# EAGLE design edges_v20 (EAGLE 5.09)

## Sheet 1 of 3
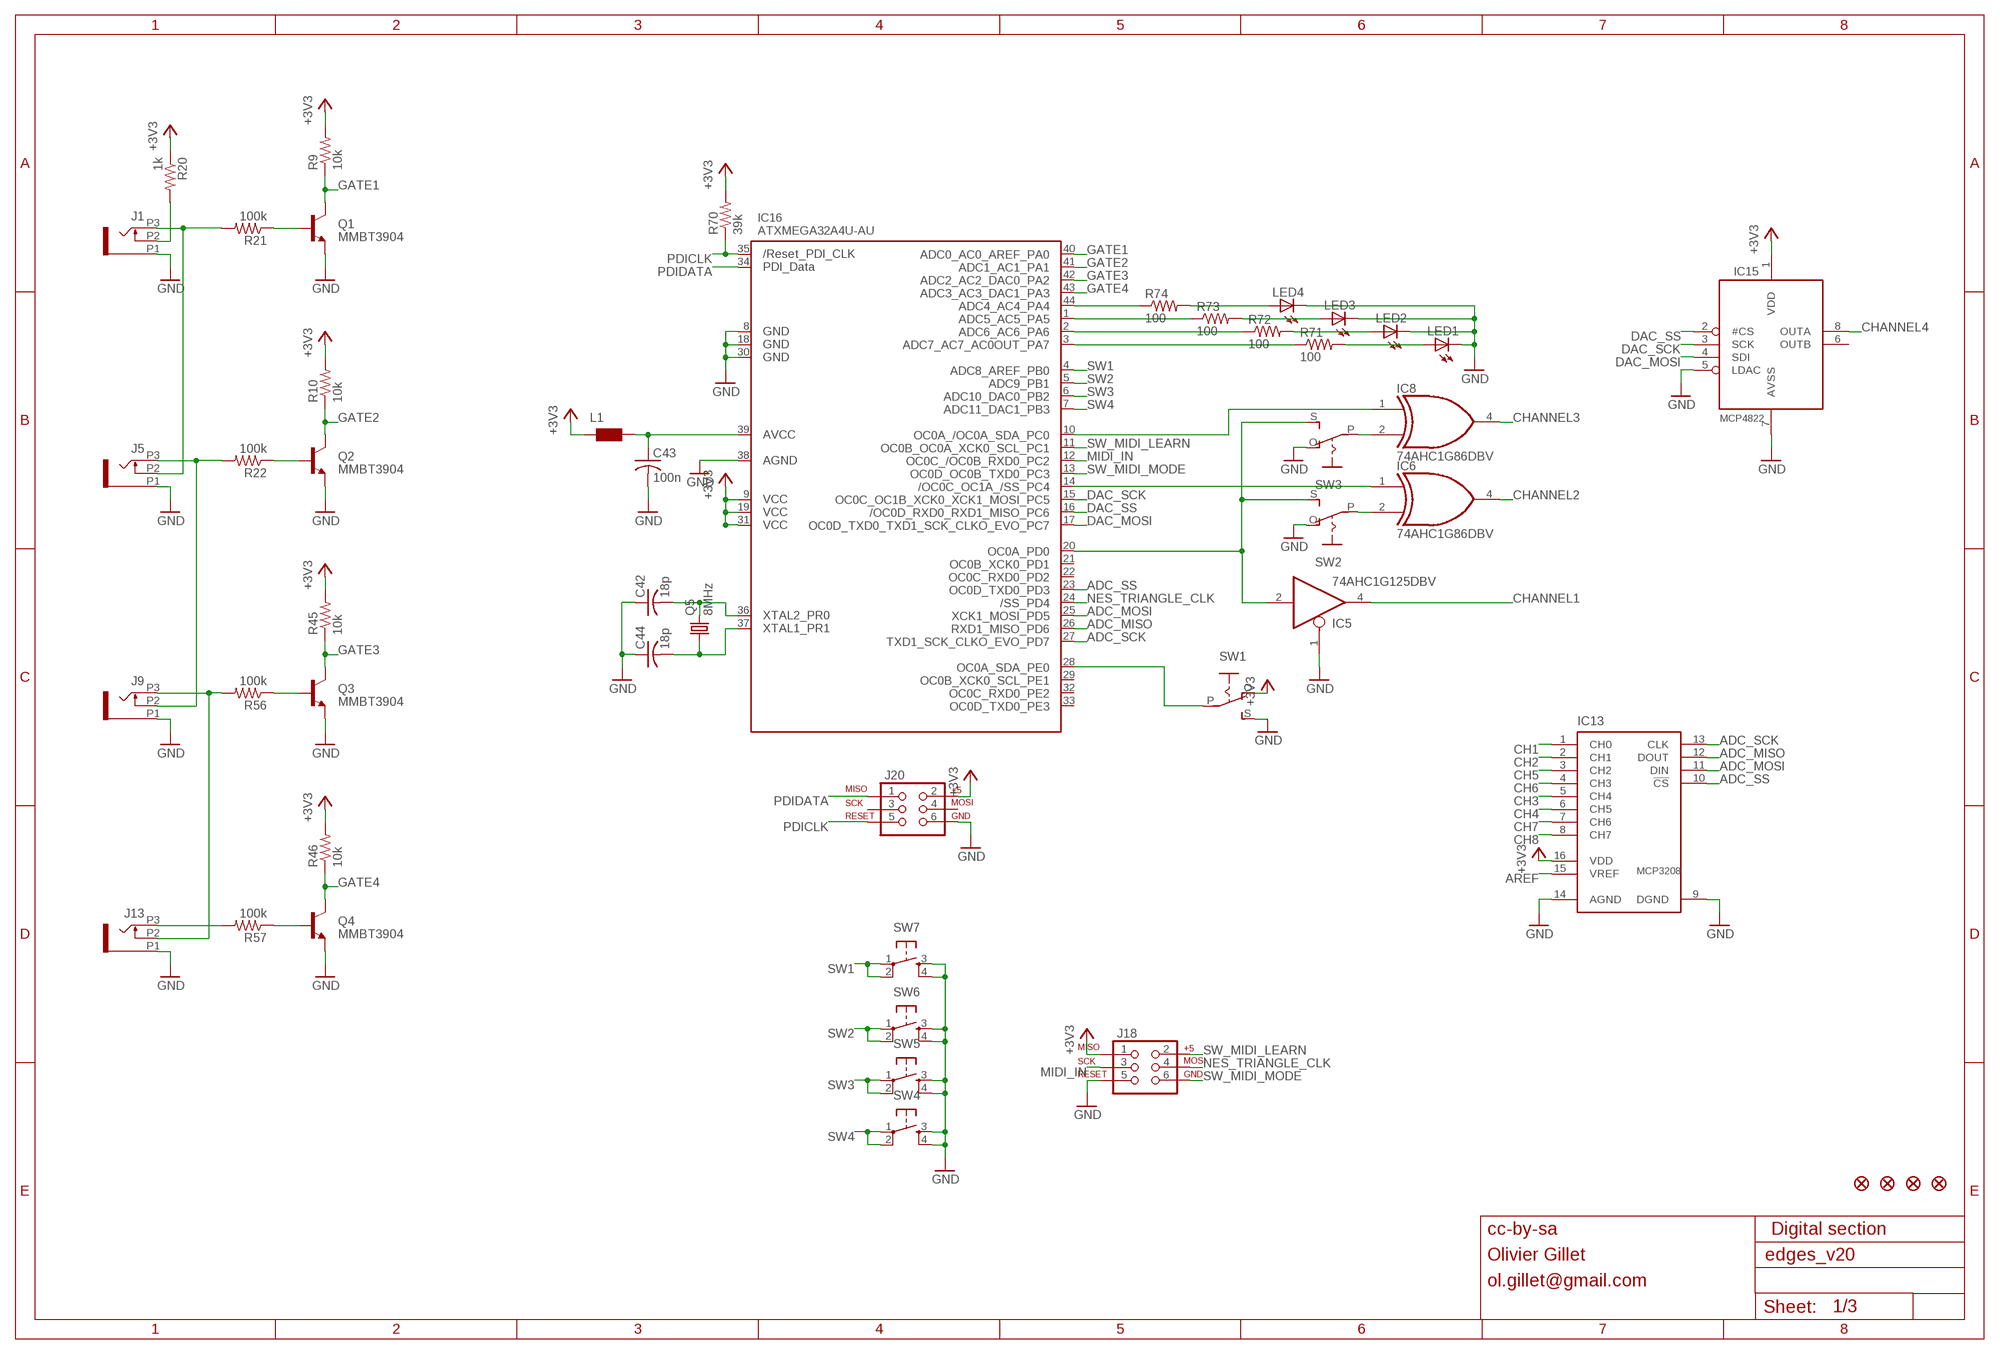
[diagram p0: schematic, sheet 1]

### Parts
C42  18p  C-USC0603  [C0603]
C43  100n  C-USC0603  [C0603]
C44  18p  C-USC0603  [C0603]
IC5  74AHC1G125DBV  [SOT23-5]
IC6  74AHC1G86DBV  [SOT23-5]
IC8  74AHC1G86DBV  [SOT23-5]
IC13  MCP3208  [SO16]
IC15  MCP4822  MCP4822SO08  [SO08]
IC16  ATXMEGA32A4U-AU  AVR_XMEGA_A4_44A  [TQFP44]
J1  PJ301_THONKICONN6  [WQP_PJ_301M6]
J5  PJ301_THONKICONN6  [WQP_PJ_301M6]
J9  PJ301_THONKICONN6  [WQP_PJ_301M6]
J13  PJ301_THONKICONN6  [WQP_PJ_301M6]
J18  AVR_SPI_PRG_6PTH  [2X3]
J20  AVR_SPI_PRG_6PTH  [2X3]
JP1  FIDUCIAL1X2  [FIDUCIAL-1X2]
JP2  FIDUCIAL1X2  [FIDUCIAL-1X2]
JP3  FIDUCIAL1X2  [FIDUCIAL-1X2]
JP4  FIDUCIAL1X2  [FIDUCIAL-1X2]
L1  WE-CBF_0603  [0603]
LED1  LED3MM  [LED3MM]
LED2  LED3MM  [LED3MM]
LED3  LED3MM  [LED3MM]
LED4  LED3MM  [LED3MM]
Q1  MMBT3904  MMBT3904LT1-NPN-SOT23-BEC  [SOT23-BEC]
Q2  MMBT3904  MMBT3904LT1-NPN-SOT23-BEC  [SOT23-BEC]
Q3  MMBT3904  MMBT3904LT1-NPN-SOT23-BEC  [SOT23-BEC]
Q4  MMBT3904  MMBT3904LT1-NPN-SOT23-BEC  [SOT23-BEC]
Q5  8MHz  CRYSTALHC49U70  [HC49U70]
R9  10k  R-US_R0603  [R0603]
R10  10k  R-US_R0603  [R0603]
R20  1k  R-US_R0603  [R0603]
R21  100k  R-US_R0603  [R0603]
R22  100k  R-US_R0603  [R0603]
R45  10k  R-US_R0603  [R0603]
R46  10k  R-US_R0603  [R0603]
R56  100k  R-US_R0603  [R0603]
R57  100k  R-US_R0603  [R0603]
R70  39k  R-US_R0603  [R0603]
R71  100  R-US_R0603  [R0603]
R72  100  R-US_R0603  [R0603]
R73  100  R-US_R0603  [R0603]
R74  100  R-US_R0603  [R0603]
SW1  S-ON-ONSMALL_SLIDE  [ES_100SP1T6B11M2QEH_SMALL]
SW2  S-ON-ONSMALL_SLIDE  [ES_100SP1T6B11M2QEH_SMALL]
SW3  S-ON-ONSMALL_SLIDE  [ES_100SP1T6B11M2QEH_SMALL]
SW4  TAC_SWITCHPTH  [TACTILE-PTH]
SW5  TAC_SWITCHPTH  [TACTILE-PTH]
SW6  TAC_SWITCHPTH  [TACTILE-PTH]
SW7  TAC_SWITCHPTH  [TACTILE-PTH]

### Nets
+3V3: IC13.16(VDD) IC15.1(VDD) IC16.9(VCC1) IC16.19(VCC2) IC16.31(VCC3) J18.1 J20.2 L1.1 R9.2 R10.2 R20.1 R45.2 R46.2 R70.2 SW1.O ; also sheet 3
ADC_MISO: IC13.12(DOUT) IC16.26(PD6)
ADC_MOSI: IC13.11(DIN) IC16.25(PD5)
ADC_SCK: IC13.13(CLK) IC16.27(PD7)
ADC_SS: IC13.10(!CS) IC16.23(PD3)
AREF: IC13.15(VREF) ; also sheet 3
CH1: IC13.1(CH0) ; also sheet 2
CH2: IC13.2(CH1) ; also sheet 2
CH3: IC13.5(CH4) ; also sheet 2
CH4: IC13.6(CH5) ; also sheet 2
CH5: IC13.3(CH2) ; also sheet 2
CH6: IC13.4(CH3) ; also sheet 2
CH7: IC13.7(CH6) ; also sheet 2
CH8: IC13.8(CH7) ; also sheet 2
CHANNEL1: IC5.4(O) ; also sheet 2
CHANNEL2: IC6.4(O) ; also sheet 2
CHANNEL3: IC8.4(O) ; also sheet 2
CHANNEL4: IC15.8(OUTA) ; also sheet 2
DAC_MOSI: IC15.4(SDI) IC16.17(PC7)
DAC_SCK: IC15.3(SCK) IC16.15(PC5)
DAC_SS: IC15.2(#CS) IC16.16(PC6)
GATE1: IC16.40(PA0) Q1.C R9.1
GATE1_IN: J1.P3 J5.P2 R21.2
GATE1_LED: LED4.A R74.2
GATE2: IC16.41(PA1) Q2.C R10.1
GATE2_IN: J5.P3 J9.P2 R22.2
GATE2_LED: LED3.A R73.2
GATE3: IC16.42(PA2) Q3.C R45.1
GATE3_IN: J9.P3 J13.P2 R56.2
GATE3_LED: LED2.A R72.2
GATE4: IC16.43(PA3) Q4.C R46.1
GATE4_IN: J13.P3 R57.2
GATE4_LED: LED1.A R71.2
GND: C42.1 C43.2 C44.1 IC5.1(OE) IC13.9(DGND) IC13.14(AGND) IC15.5(LDAC) IC15.7(AVSS) IC16.8(GND1) IC16.18(GND2) IC16.30(GND3) IC16.38(AGND) J1.P1 J5.P1 J9.P1 J13.P1 J18.5 J20.6 LED1.K(C) LED2.K(C) LED3.K(C) LED4.K(C) Q1.E Q2.E Q3.E Q4.E SW1.S SW2.O SW3.O SW4.3 SW4.4 SW5.3 SW5.4 SW6.3 SW6.4 SW7.3 SW7.4 ; also sheet 2,3
MIDI_IN: IC16.12(PC2) J18.3
N$1: Q1.B R21.1
N$2: Q2.B R22.1
N$3: Q3.B R56.1
N$5: IC16.44(PA4) R74.1
N$6: IC16.1(PA5) R73.1
N$7: IC16.2(PA6) R72.1
N$8: IC16.3(PA7) R71.1
N$12: J1.P2 R20.2
N$19: IC6.1(I0) IC16.14(PC4)
N$21: IC8.2(I1) SW3.P
N$24: IC6.2(I1) SW2.P
N$39: C43.1 IC16.39(AVCC) L1.2
N$41: IC8.1(I0) IC16.10(PC0)
N$48: IC5.2(I) IC16.20(PD0) SW2.S SW3.S
N$82: C44.2 IC16.37(PR1) Q5.1
N$83: C42.2 IC16.36(PR0) Q5.2
N$40000: Q4.B R57.1
NES_TRIANGLE_CLK: IC16.24(PD4) J18.4
PDICLK: IC16.35(RESET) J20.5 R70.1
PDIDATA: IC16.34(PDI_DATA) J20.1
SW1: IC16.4(PB0) SW7.1 SW7.2
SW2: IC16.5(PB1) SW6.1 SW6.2
SW3: IC16.6(PB2) SW5.1 SW5.2
SW4: IC16.7(PB3) SW4.1 SW4.2
SW_MIDI_LEARN: IC16.11(PC1) J18.2
SW_MIDI_MODE: IC16.13(PC3) J18.6
SYNC_SWITCH: IC16.28(PE0) SW1.P
Unconnected: IC15.6(OUTB) IC16.21(PD1) IC16.22(PD2) IC16.29(PE1) IC16.32(PE2) IC16.33(PE3) J20.3 J20.4

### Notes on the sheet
- cc-by-sa | Digital section
- Olivier Gillet
- ol.gillet@gmail.com

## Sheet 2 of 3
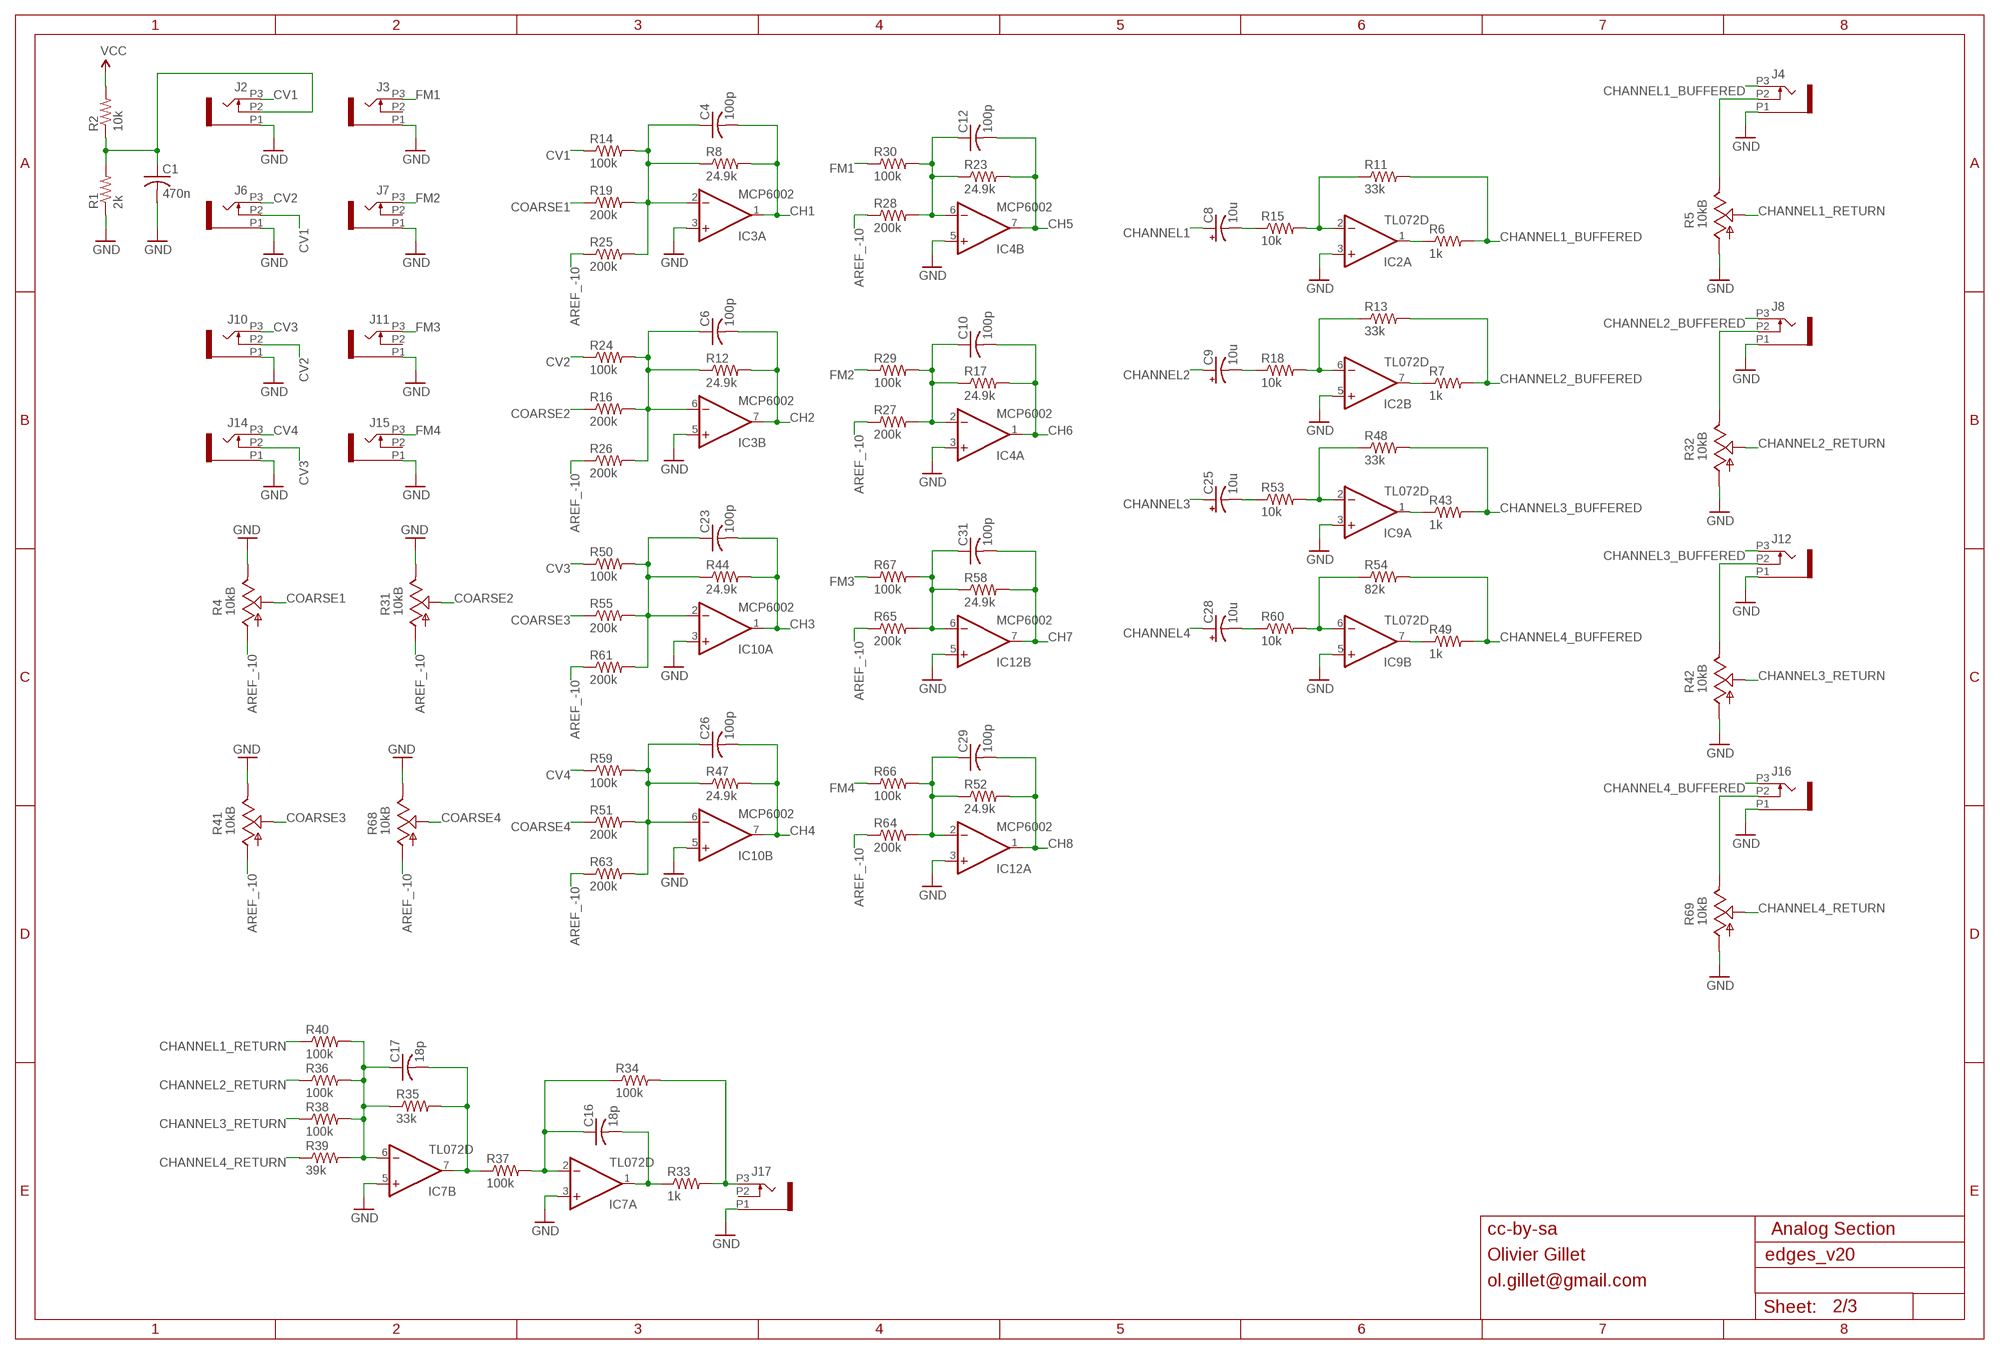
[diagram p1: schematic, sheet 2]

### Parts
C1  470n  C-USC0603  [C0603]
C4  100p  C-USC0603  [C0603]
C6  100p  C-USC0603  [C0603]
C8  10u  CPOL-USB  [PANASONIC_B]
C9  10u  CPOL-USB  [PANASONIC_B]
C10  100p  C-USC0603  [C0603]
C12  100p  C-USC0603  [C0603]
C16  18p  C-USC0603  [C0603]
C17  18p  C-USC0603  [C0603]
C23  100p  C-USC0603  [C0603]
C25  10u  CPOL-USB  [PANASONIC_B]
C26  100p  C-USC0603  [C0603]
C28  10u  CPOL-USB  [PANASONIC_B]
C29  100p  C-USC0603  [C0603]
C31  100p  C-USC0603  [C0603]
IC2  TL072D  [SO08]
IC3  MCP6002  TL072D  [SO08]
IC4  MCP6002  TL072D  [SO08]
IC7  TL072D  [SO08]
IC9  TL072D  [SO08]
IC10  MCP6002  TL072D  [SO08]
IC12  MCP6002  TL072D  [SO08]
J2  PJ301_THONKICONN6  [WQP_PJ_301M6]
J3  PJ301_THONKICONN6  [WQP_PJ_301M6]
J4  PJ301_THONKICONN6  [WQP_PJ_301M6]
J6  PJ301_THONKICONN6  [WQP_PJ_301M6]
J7  PJ301_THONKICONN6  [WQP_PJ_301M6]
J8  PJ301_THONKICONN6  [WQP_PJ_301M6]
J10  PJ301_THONKICONN6  [WQP_PJ_301M6]
J11  PJ301_THONKICONN6  [WQP_PJ_301M6]
J12  PJ301_THONKICONN6  [WQP_PJ_301M6]
J14  PJ301_THONKICONN6  [WQP_PJ_301M6]
J15  PJ301_THONKICONN6  [WQP_PJ_301M6]
J16  PJ301_THONKICONN6  [WQP_PJ_301M6]
J17  PJ301_THONKICONN6  [WQP_PJ_301M6]
R1  2k  R-US_R0603  [R0603]
R2  10k  R-US_R0603  [R0603]
R4  10kB  POT_USVERTICAL_PS  [ALPS_POT_VERTICAL_PS]
R5  10kB  POT_USVERTICAL_PS  [ALPS_POT_VERTICAL_PS]
R6  1k  R-US_R0603  [R0603]
R7  1k  R-US_R0603  [R0603]
R8  24.9k  R-US_R0603  [R0603]
R11  33k  R-US_R0603  [R0603]
R12  24.9k  R-US_R0603  [R0603]
R13  33k  R-US_R0603  [R0603]
R14  100k  R-US_R0603  [R0603]
R15  10k  R-US_R0603  [R0603]
R16  200k  R-US_R0603  [R0603]
R17  24.9k  R-US_R0603  [R0603]
R18  10k  R-US_R0603  [R0603]
R19  200k  R-US_R0603  [R0603]
R23  24.9k  R-US_R0603  [R0603]
R24  100k  R-US_R0603  [R0603]
R25  200k  R-US_R0603  [R0603]
R26  200k  R-US_R0603  [R0603]
R27  200k  R-US_R0603  [R0603]
R28  200k  R-US_R0603  [R0603]
R29  100k  R-US_R0603  [R0603]
R30  100k  R-US_R0603  [R0603]
R31  10kB  POT_USVERTICAL_PS  [ALPS_POT_VERTICAL_PS]
R32  10kB  POT_USVERTICAL_PS  [ALPS_POT_VERTICAL_PS]
R33  1k  R-US_R0603  [R0603]
R34  100k  R-US_R0603  [R0603]
R35  33k  R-US_R0603  [R0603]
R36  100k  R-US_R0603  [R0603]
R37  100k  R-US_R0603  [R0603]
R38  100k  R-US_R0603  [R0603]
R39  39k  R-US_R0603  [R0603]
R40  100k  R-US_R0603  [R0603]
R41  10kB  POT_USVERTICAL_PS  [ALPS_POT_VERTICAL_PS]
R42  10kB  POT_USVERTICAL_PS  [ALPS_POT_VERTICAL_PS]
R43  1k  R-US_R0603  [R0603]
R44  24.9k  R-US_R0603  [R0603]
R47  24.9k  R-US_R0603  [R0603]
R48  33k  R-US_R0603  [R0603]
R49  1k  R-US_R0603  [R0603]
R50  100k  R-US_R0603  [R0603]
R51  200k  R-US_R0603  [R0603]
R52  24.9k  R-US_R0603  [R0603]
R53  10k  R-US_R0603  [R0603]
R54  82k  R-US_R0603  [R0603]
R55  200k  R-US_R0603  [R0603]
R58  24.9k  R-US_R0603  [R0603]
R59  100k  R-US_R0603  [R0603]
R60  10k  R-US_R0603  [R0603]
R61  200k  R-US_R0603  [R0603]
R63  200k  R-US_R0603  [R0603]
R64  200k  R-US_R0603  [R0603]
R65  200k  R-US_R0603  [R0603]
R66  100k  R-US_R0603  [R0603]
R67  100k  R-US_R0603  [R0603]
R68  10kB  POT_USVERTICAL_PS  [ALPS_POT_VERTICAL_PS]
R69  10kB  POT_USVERTICAL_PS  [ALPS_POT_VERTICAL_PS]

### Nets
AREF_-10: R4.P$3(A) R25.1 R26.1 R27.1 R28.1 R31.P$3(A) R41.P$3(A) R61.1 R63.1 R64.1 R65.1 R68.P$3(A) ; also sheet 3
CH1: C4.2 IC3.1(A:OUT) R8.2 ; also sheet 1
CH2: C6.2 IC3.7(B:OUT) R12.2 ; also sheet 1
CH3: C23.2 IC10.1(A:OUT) R44.2 ; also sheet 1
CH4: C26.2 IC10.7(B:OUT) R47.2 ; also sheet 1
CH5: C12.2 IC4.7(B:OUT) R23.2 ; also sheet 1
CH6: C10.2 IC4.1(A:OUT) R17.2 ; also sheet 1
CH7: C31.2 IC12.7(B:OUT) R58.2 ; also sheet 1
CH8: C29.2 IC12.1(A:OUT) R52.2 ; also sheet 1
CHANNEL1: C8.+ ; also sheet 1
CHANNEL1_BUFFERED: J4.P3 R6.2 R11.2
CHANNEL1_RETURN: R5.P$2(S) R40.1
CHANNEL2: C9.+ ; also sheet 1
CHANNEL2_BUFFERED: J8.P3 R7.2 R13.2
CHANNEL2_RETURN: R32.P$2(S) R36.1
CHANNEL3: C25.+ ; also sheet 1
CHANNEL3_BUFFERED: J12.P3 R43.2 R48.2
CHANNEL3_RETURN: R38.1 R42.P$2(S)
CHANNEL4: C28.+ ; also sheet 1
CHANNEL4_BUFFERED: J16.P3 R49.2 R54.2
CHANNEL4_RETURN: R39.1 R69.P$2(S)
COARSE1: R4.P$2(S) R19.1
COARSE2: R16.1 R31.P$2(S)
COARSE3: R41.P$2(S) R55.1
COARSE4: R51.1 R68.P$2(S)
CV1: J2.P3 J6.P2 R14.1
CV2: J6.P3 J10.P2 R24.1
CV3: J10.P3 J14.P2 R50.1
CV4: J14.P3 R59.1
FM1: J3.P3 R30.1
FM2: J7.P3 R29.1
FM3: J11.P3 R67.1
FM4: J15.P3 R66.1
GND: C1.2 IC2.3(A:+IN) IC2.5(B:+IN) IC3.3(A:+IN) IC3.5(B:+IN) IC4.3(A:+IN) IC4.5(B:+IN) IC7.3(A:+IN) IC7.5(B:+IN) IC9.3(A:+IN) IC9.5(B:+IN) IC10.3(A:+IN) IC10.5(B:+IN) IC12.3(A:+IN) IC12.5(B:+IN) J2.P1 J3.P1 J4.P1 J6.P1 J7.P1 J8.P1 J10.P1 J11.P1 J12.P1 J14.P1 J15.P1 J16.P1 J17.P1 R1.1 R4.P$1(E) R5.P$3(A) R31.P$1(E) R32.P$3(A) R41.P$1(E) R42.P$3(A) R68.P$1(E) R69.P$3(A) ; also sheet 1,3
MIX: J17.P3 R33.2 R34.2
N$4: J8.P2 R32.P$1(E)
N$9: C23.1 IC10.2(A:-IN) R44.1 R50.2 R55.2 R61.2
N$11: C10.1 IC4.2(A:-IN) R17.1 R27.2 R29.2
N$13: C26.1 IC10.6(B:-IN) R47.1 R51.2 R59.2 R63.2
N$15: C31.1 IC12.6(B:-IN) R58.1 R65.2 R67.2
N$18: C29.1 IC12.2(A:-IN) R52.1 R64.2 R66.2
N$20: C8.- R15.1
N$22: IC2.2(A:-IN) R11.1 R15.2
N$23: IC2.1(A:OUT) R6.1
N$25: C9.- R18.1
N$26: IC2.6(B:-IN) R13.1 R18.2
N$27: IC2.7(B:OUT) R7.1
N$28: C25.- R53.1
N$29: C12.1 IC4.6(B:-IN) R23.1 R28.2 R30.2
N$30: IC9.2(A:-IN) R48.1 R53.2
N$31: IC9.1(A:OUT) R43.1
N$32: C28.- R60.1
N$33: IC9.6(B:-IN) R54.1 R60.2
N$34: IC9.7(B:OUT) R49.1
N$35: C17.1 IC7.6(B:-IN) R35.1 R36.2 R38.2 R39.2 R40.2
N$36: C16.1 IC7.2(A:-IN) R34.1 R37.2
N$37: C16.2 IC7.1(A:OUT) R33.1
N$40: J4.P2 R5.P$1(E)
N$42: C17.2 IC7.7(B:OUT) R35.2 R37.1
N$43: J12.P2 R42.P$1(E)
N$44: J16.P2 R69.P$1(E)
N$45: C6.1 IC3.6(B:-IN) R12.1 R16.2 R24.2 R26.2
N$46: C1.1 J2.P2 R1.2 R2.1
N$50: C4.1 IC3.2(A:-IN) R8.1 R14.2 R19.2 R25.2
VCC: R2.2 ; also sheet 3
Unconnected: J3.P2 J7.P2 J11.P2 J15.P2 J17.P2

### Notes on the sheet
- cc-by-sa | Analog Section
- Olivier Gillet
- ol.gillet@gmail.com

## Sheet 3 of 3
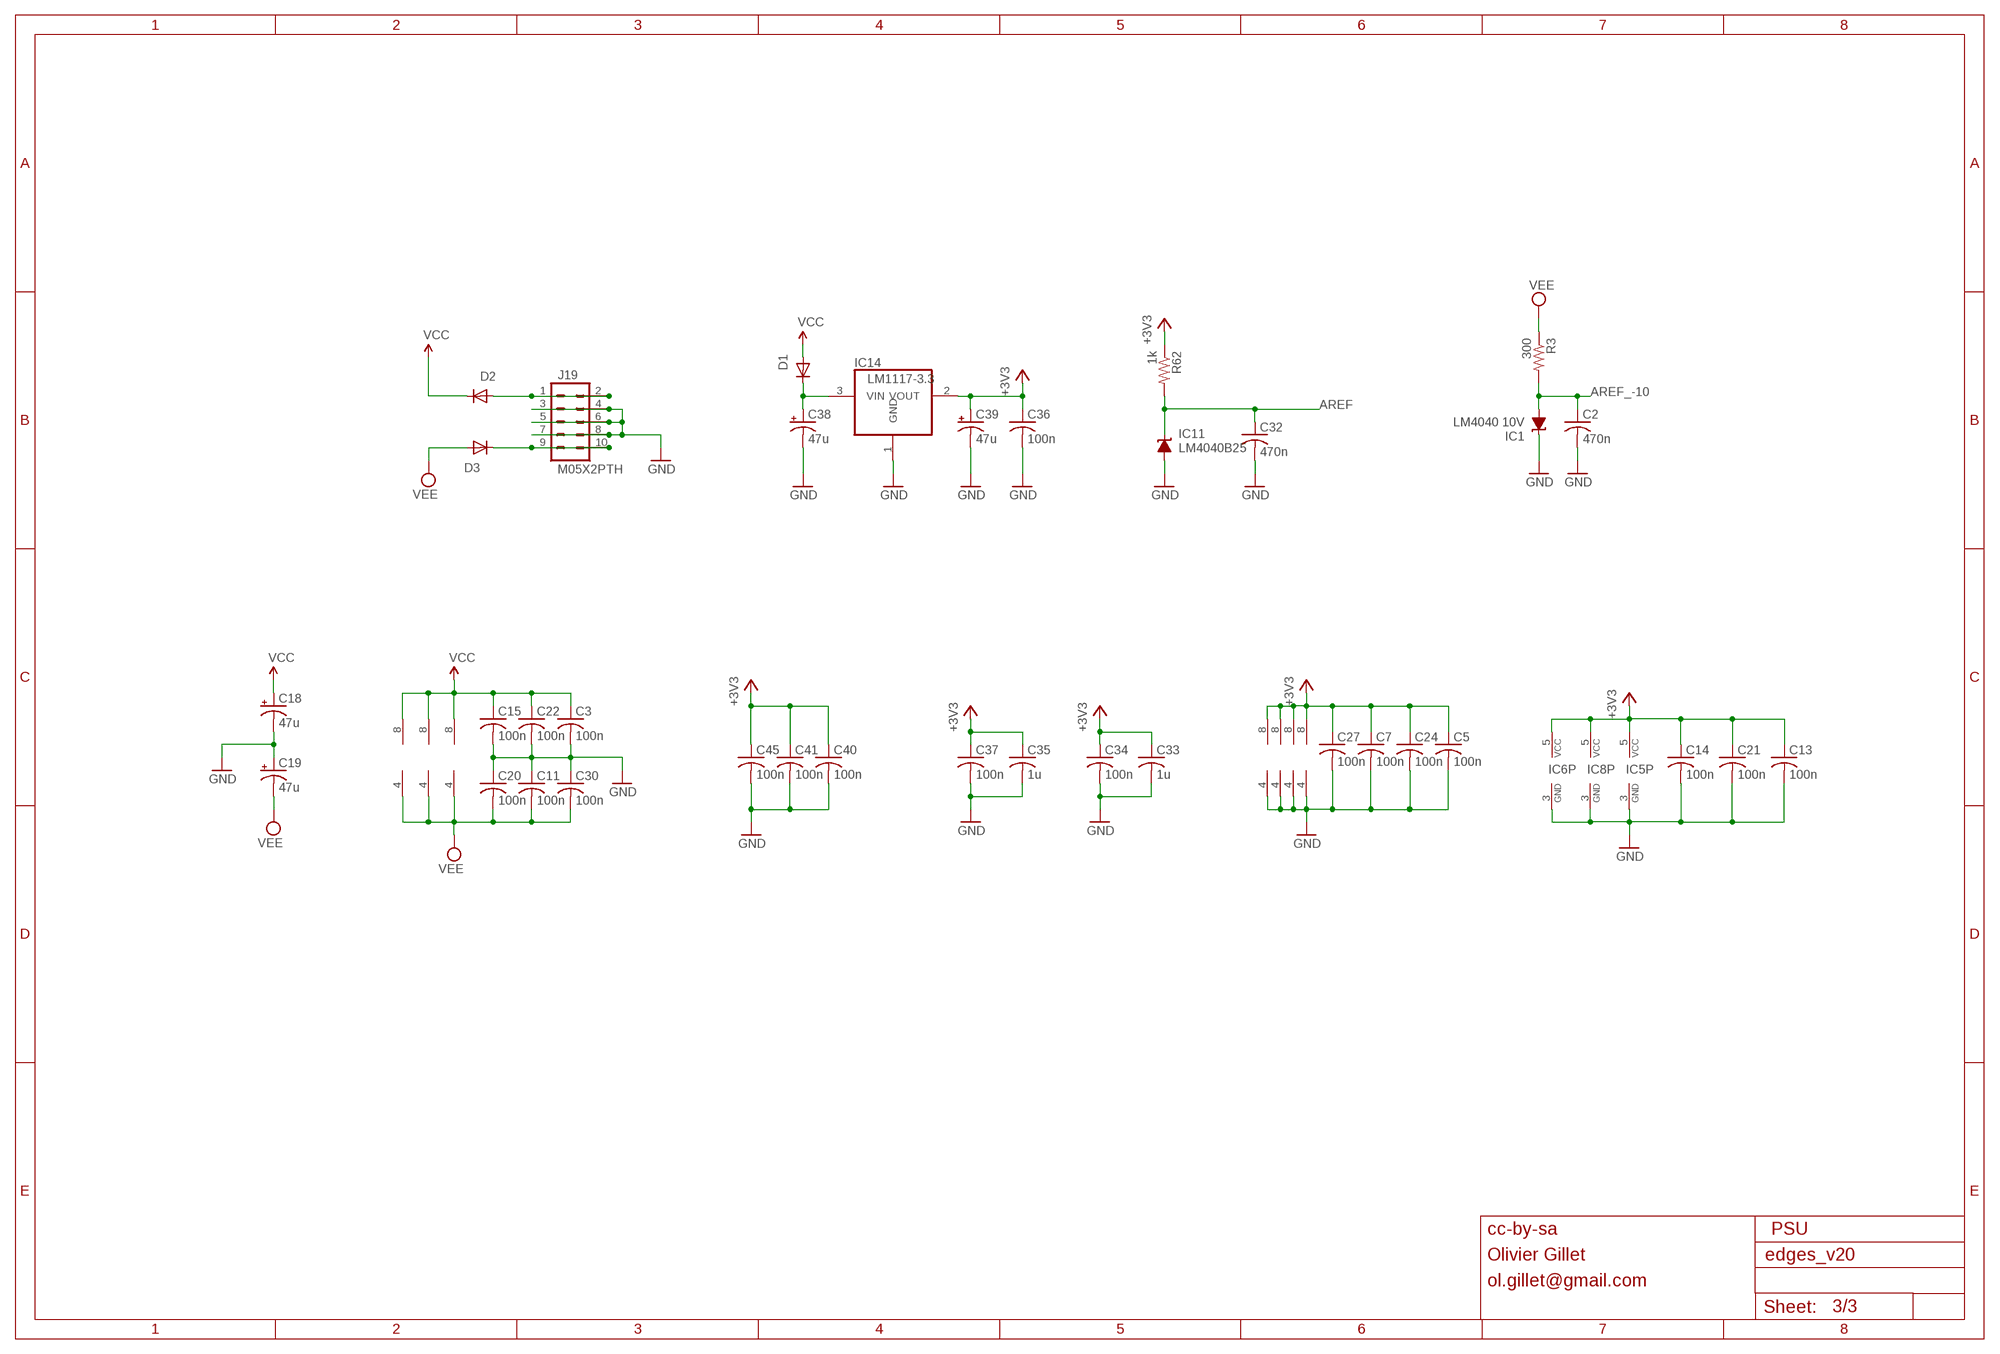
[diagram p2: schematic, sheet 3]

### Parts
C2  470n  C-USC0603  [C0603]
C3  100n  C-USC0603  [C0603]
C5  100n  C-USC0603  [C0603]
C7  100n  C-USC0603  [C0603]
C11  100n  C-USC0603  [C0603]
C13  100n  C-USC0603  [C0603]
C14  100n  C-USC0603  [C0603]
C15  100n  C-USC0603  [C0603]
C18  47u  CPOL-USD  [PANASONIC_D]
C19  47u  CPOL-USD  [PANASONIC_D]
C20  100n  C-USC0603  [C0603]
C21  100n  C-USC0603  [C0603]
C22  100n  C-USC0603  [C0603]
C24  100n  C-USC0603  [C0603]
C27  100n  C-USC0603  [C0603]
C30  100n  C-USC0603  [C0603]
C32  470n  C-USC0603  [C0603]
C33  1u  C-USC0603  [C0603]
C34  100n  C-USC0603  [C0603]
C35  1u  C-USC0603  [C0603]
C36  100n  C-USC0603  [C0603]
C37  100n  C-USC0603  [C0603]
C38  47u  CPOL-USD  [PANASONIC_D]
C39  47u  CPOL-USD  [PANASONIC_D]
C40  100n  C-USC0603  [C0603]
C41  100n  C-USC0603  [C0603]
C45  100n  C-USC0603  [C0603]
D1  1N5819HW  DIODE-SOD123  [SOD123]
D2  1N5819HW  DIODE-SOD123  [SOD123]
D3  1N5819HW  DIODE-SOD123  [SOD123]
IC1  LM4040 10V  LM4041C12DBZ  [DBZ_R-PDSO-G3]
IC11  LM4040B25  LM4041B12DBZ  [DBZ_R-PDSO-G3]
IC14  LM1117-3.3  REG1117  [SOT223]
J19  M05X2PTH  [AVR_ICSP]
R3  300  R-US_R0603  [R0603]
R62  1k  R-US_R0603  [R0603]

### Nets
+3V3: C5.1 C7.1 C13.1 C14.1 C21.1 C24.1 C27.1 C33.1 C34.1 C35.1 C36.1 C37.1 C39.+ C40.1 C41.1 C45.1 IC3.8(P:V+) IC4.8(P:V+) IC5.5(VCC) IC6.5(VCC) IC8.5(VCC) IC10.8(P:V+) IC12.8(P:V+) IC14.2(VOUT) R62.1 ; also sheet 1
AREF: C32.1 IC11.1(C) R62.2 ; also sheet 1
AREF_-10: C2.1 IC1.2(A) R3.2 ; also sheet 2
GND: C2.2 C3.2 C5.2 C7.2 C11.1 C13.2 C14.2 C15.2 C18.- C19.+ C20.1 C21.2 C22.2 C24.2 C27.2 C30.1 C32.2 C33.2 C34.2 C35.2 C36.2 C37.2 C38.- C39.- C40.2 C41.2 C45.2 IC1.1(C) IC3.4(P:V-) IC4.4(P:V-) IC5.3(GND) IC6.3(GND) IC8.3(GND) IC10.4(P:V-) IC11.2(A) IC12.4(P:V-) IC14.1(GND) J19.3 J19.4 J19.5 J19.6 J19.7 J19.8 ; also sheet 1,2
N$38: C38.+ D1.C IC14.3(VIN)
N$47: D2.A J19.1 J19.2
N$49: D3.C J19.9 J19.10
VCC: C3.1 C15.1 C18.+ C22.1 D1.A D2.C IC2.8(P:V+) IC7.8(P:V+) IC9.8(P:V+) ; also sheet 2
VEE: C11.2 C19.- C20.2 C30.2 D3.A IC2.4(P:V-) IC7.4(P:V-) IC9.4(P:V-) R3.1

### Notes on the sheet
- cc-by-sa | PSU
- Olivier Gillet
- ol.gillet@gmail.com

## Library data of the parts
C1-C7 C10-C17 C20-C24 C26 C27 C29-C37 C40-C45 = rcl:C-US: CAPACITOR, American symbol
C8 C9 C18 C19 C25 C28 C38 C39 = rcl:CPOL-US: POLARIZED CAPACITOR, American symbol
D1-D3 = diode:DIODE-: DIODE
IC1 IC11 = texas:LM4041: PRECISION MICROPOWER SHUNT VOLTAGE REFERENCE
IC2-IC4 IC7 IC9 IC10 IC12 = og-linear:TL072: OP AMP
IC5 = 74xx-little-us:74*1G125: Single Bus Buffer Gate with 3-State Output
IC6 IC8 = 74xx-little-us:74*1G86: 2-input EXCLUSIV-OR gate
IC13 = og-adc:MCP3208
IC14 = og-vreg:REG1117: 800mA and 1A Low Dropout (LDO) Positive Regulator 1.8V, 2.5V, 2.85V, 3.3V, 5V, and Adj
IC15 = og-dac:MCP4822
IC16 = xmega:AVR_XMEGA_A4_: Device for Atmel AVR XMEGA A4 Series
J1-J17 = og-pj301:PJ301_THONKICONN
J18 J20 = SparkFun:AVR_SPI_PRG_6: AVR ISP 6 Pin This is the reduced ISP connector for AVR programming. Common on Arduino. This footprint will take up less PCB space and can be used with a 10-pin to 6-pin adapter such as SKU: BOB-08508
J19 = SparkFun:M05X2: Header 5x2 Standard 10-pin dual row 0.1" header. Commonly used with AVR-ISP. Use with Spark Fun Electronics SKU: PRT-00778
JP1-JP4 = SparkFun:FIDUCIAL: Fiducial Alignment Points
L1 = wuerth-elektronik:WE-CBF: SMD EMI Suppression Ferrite Beads
LED1-LED4 = led:LED: LED
Q1-Q4 = transistor:*-NPN-: NPN Transistror BF959 corrected 2008.03.06
Q5 = crystal:CRYSTAL: CRYSTAL
R1 R2 R6-R30 R33-R40 R43-R67 R70-R74 = rcl:R-US_: RESISTOR, American symbol
R3 = resistor:R-US_: RESISTOR, American symbol
R4 R5 R31 R32 R41 R42 R68 R69 = pot-alps:POT_US
SW1-SW3 = og-switch:S-ON-ON: On-on Switch
SW4-SW7 = SparkFun:TAC_SWITCH: Momentary Switch Button commonly used for reset or general input. Spark Fun Electronics SKU : COM-00097

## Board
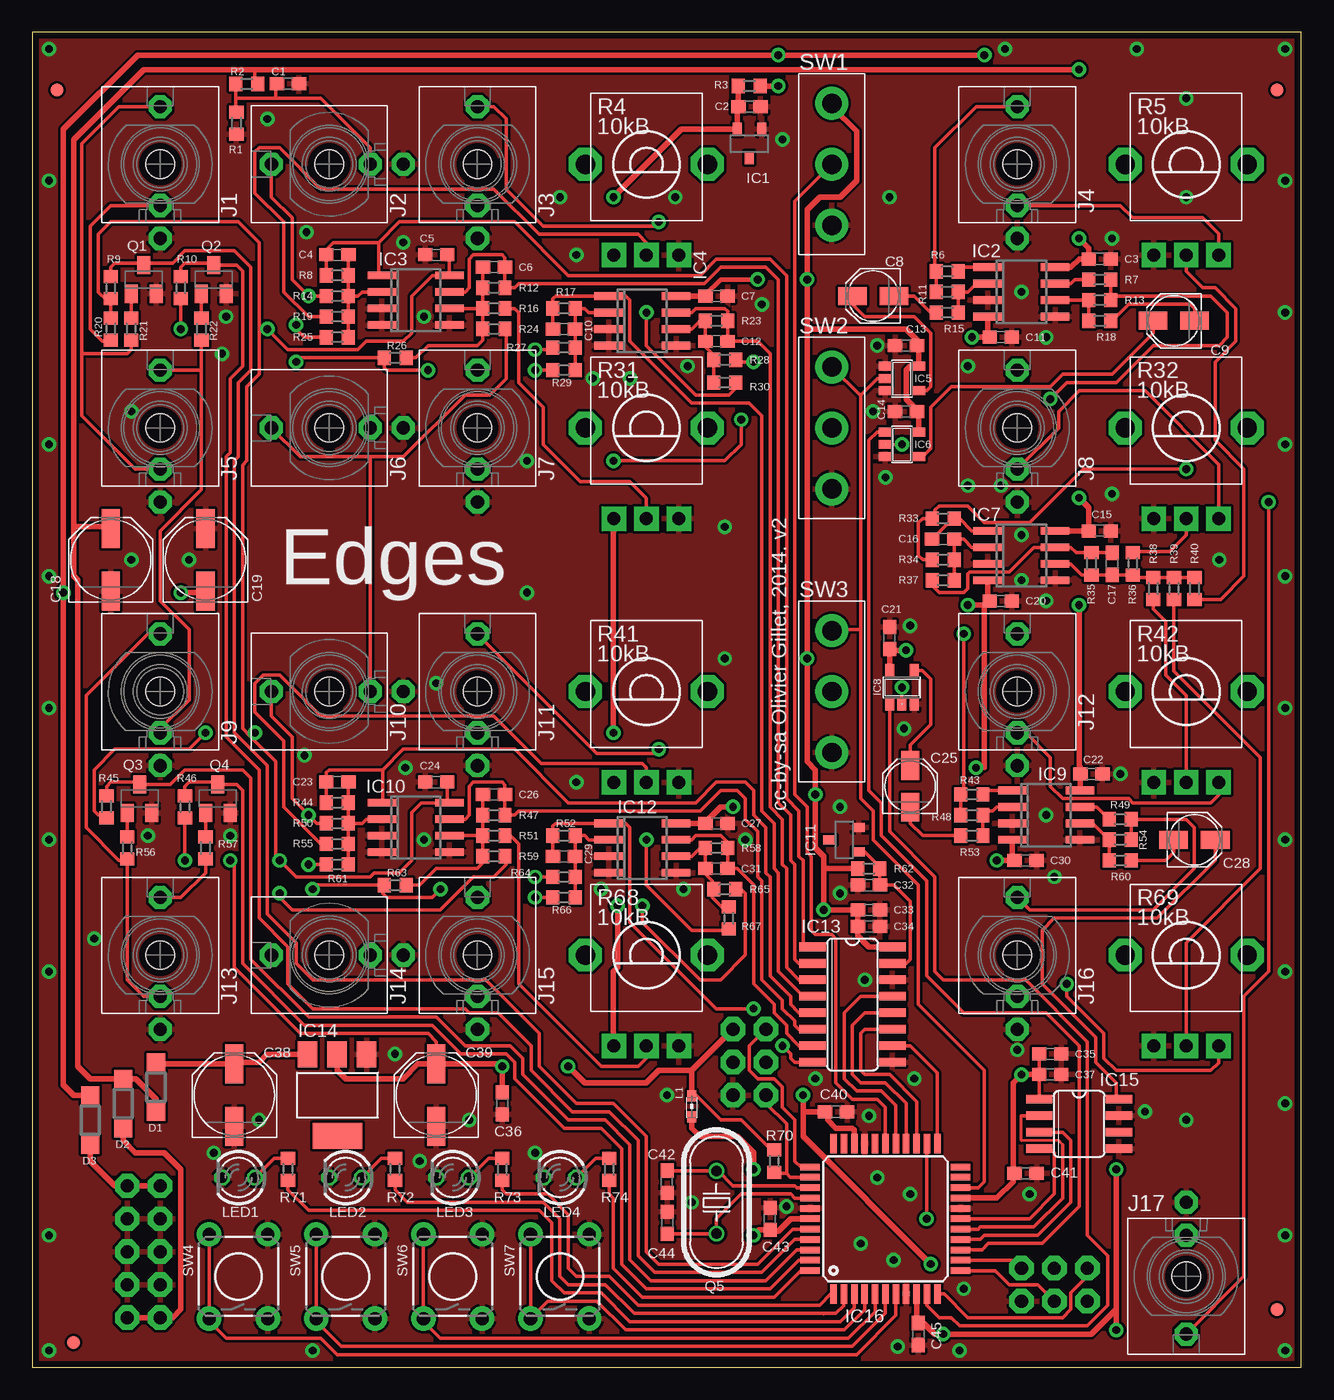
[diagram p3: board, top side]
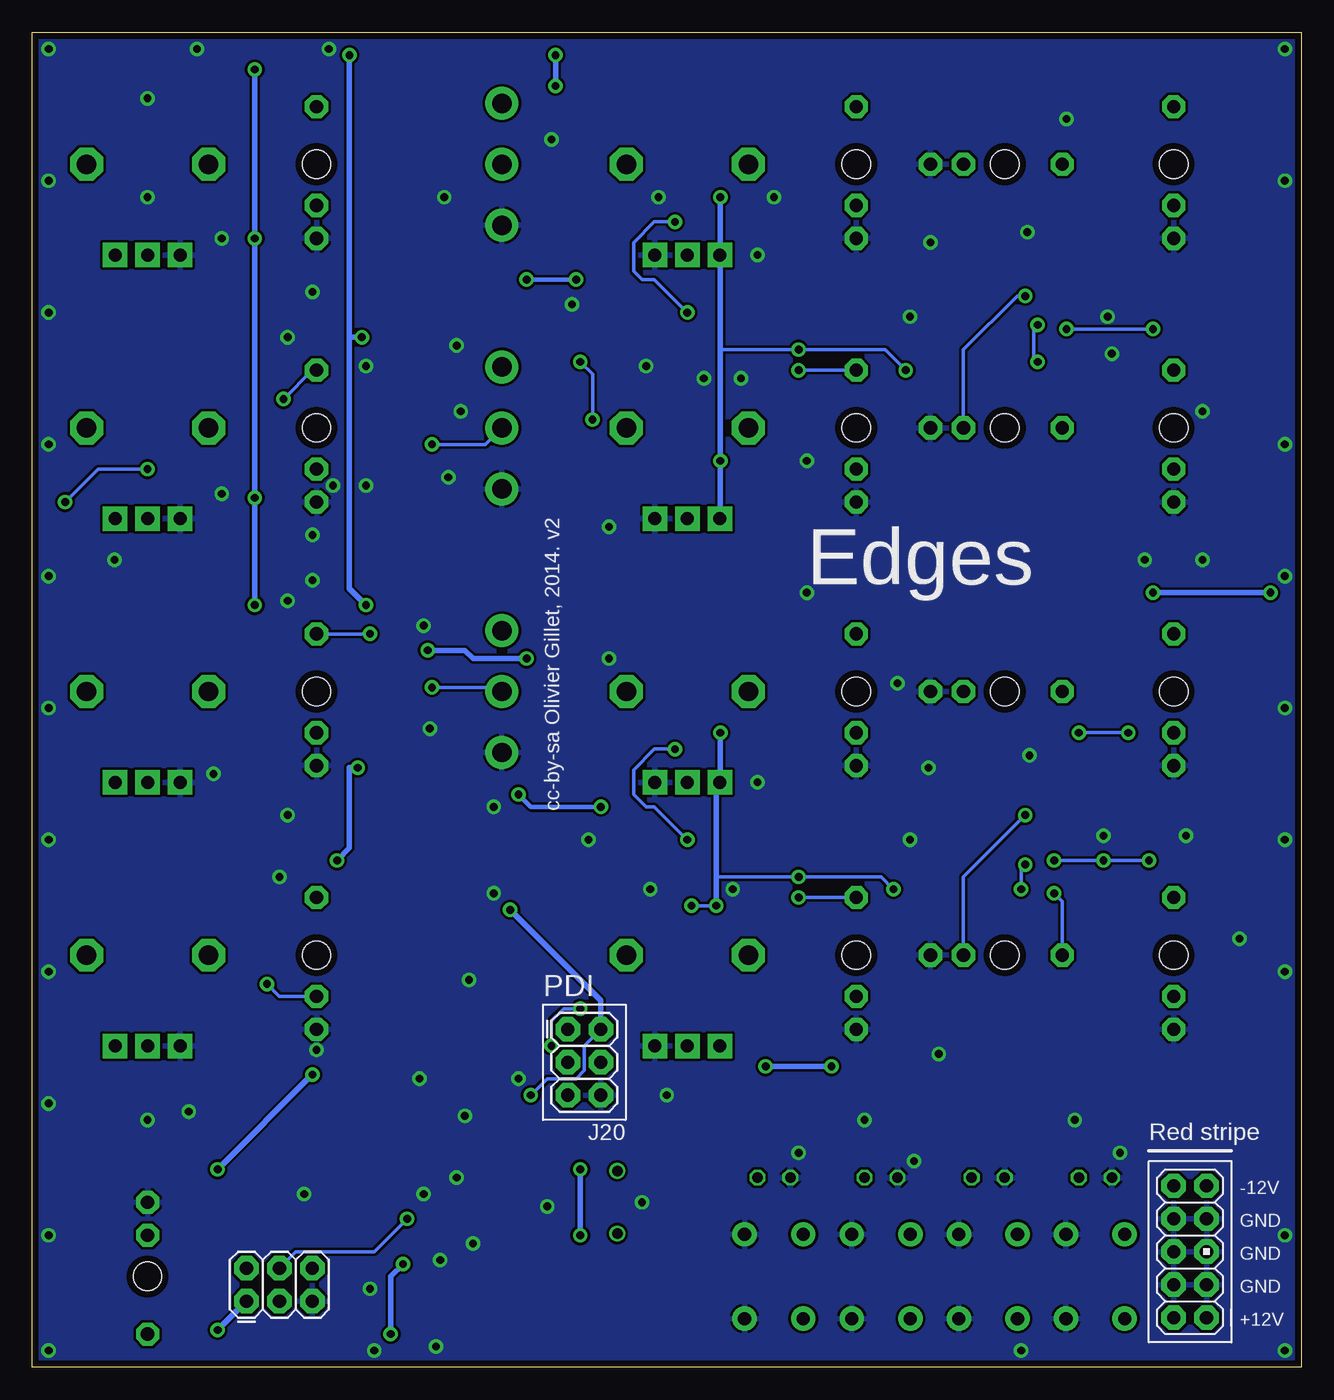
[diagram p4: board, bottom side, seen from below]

Size 97.77 x 102.87 mm. Coordinates in mm from the lower left corner, seen from the top.
Outline: 0,0 97.77,0 97.77,102.87 0,102.87 0,0
Copper layers (1*16): Top 0.035mm / dielectric 1.5mm / Bottom 0.035mm
Design rules "PCBCart-Standard *": minimum track width 8mil, minimum drill 0.4mm, track to track 8mil, track to pad 8mil, pad to pad 8mil, via to via 8mil, smd to smd 8mil, copper to edge 20mil, drill to drill 8mil, minimum pad ring 8mil, minimum via ring 10mil, stop-mask expansion 3mil, vias tented up to drill 25mil, thermal gap 8mil

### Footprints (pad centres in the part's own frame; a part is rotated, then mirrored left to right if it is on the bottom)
C0603 = smd 1.1 x 1: 1 -0.85,0; 2 0.85,0
PANASONIC_B = smd 2.2 x 1.4: + 1.6,0; - -1.6,0
PANASONIC_D = smd 3 x 1.4: + 2.4,0; - -2.4,0
SOD123 = smd 1.4 x 1.4: A 1.9,0; C -1.9,0
DBZ_R-PDSO-G3 = smd 0.7 x 1: 1 -0.95,-1.1; 2 0.95,-1.1; 3 0,1.1
SO08 = smd 0.6 x 2.2: 1 -1.905,-2.6; 2 -0.635,-2.6; 3 0.635,-2.6; 4 1.905,-2.6; 5 1.905,2.6; 6 0.635,2.6; 7 -0.635,2.6; 8 -1.905,2.6
SOT23-5 = smd 0.69 x 0.99: 1 -0.95,-1.29; 2 0,-1.29; 3 0.95,-1.29; 4 0.95,1.3; 5 -0.95,1.3
SO16 = smd 0.66 x 2.032: 1 -4.445,-3.073; 2 -3.175,-3.073; 3 -1.905,-3.073; 4 -0.635,-3.073; 5 0.635,-3.073; 6 1.905,-3.073; 7 3.175,-3.073; 8 4.445,-3.073; 9 4.445,3.073; 10 3.175,3.073; 11 1.905,3.073; 12 0.635,3.073; 13 -0.635,3.073; 14 -1.905,3.073; 15 -3.175,3.073; 16 -4.445,3.073
SOT223 = smd 1.499 x 2.007: 1 -2.261,-3.15; 2 0.025,-3.15; 3 2.311,-3.15 | smd 3.81 x 2.007: 4 0,3.15
SO08' = smd 0.66 x 2.032: 1 -1.905,-3.073; 2 -0.635,-3.073; 3 0.635,-3.073; 4 1.905,-3.073; 5 1.905,3.073; 6 0.635,3.073; 7 -0.635,3.073; 8 -1.905,3.073
TQFP44 = smd 1.5 x 0.5: 1 -5.8,4; 2 -5.8,3.2; 3 -5.8,2.4; 4 -5.8,1.6; 5 -5.8,0.8; 6 -5.8,0; 7 -5.8,-0.8; 8 -5.8,-1.6; 9 -5.8,-2.4; 10 -5.8,-3.2; 11 -5.8,-4; 23 5.8,-4; 24 5.8,-3.2; 25 5.8,-2.4; 26 5.8,-1.6; 27 5.8,-0.8; 28 5.8,0; 29 5.8,0.8; 30 5.8,1.6; 31 5.8,2.4; 32 5.8,3.2; 33 5.8,4 | smd 0.5 x 1.5: 12 -4,-5.8; 13 -3.2,-5.8; 14 -2.4,-5.8; 15 -1.6,-5.8; 16 -0.8,-5.8; 17 0,-5.8; 18 0.8,-5.8; 19 1.6,-5.8; 20 2.4,-5.8; 21 3.2,-5.8; 22 4,-5.8; 34 4,5.8; 35 3.2,5.8; 36 2.4,5.8; 37 1.6,5.8; 38 0.8,5.8; 39 0,5.8; 40 -0.8,5.8; 41 -1.6,5.8; 42 -2.4,5.8; 43 -3.2,5.8; 44 -4,5.8
WQP_PJ_301M6 = drill 1.016 pad 1.778 octagon: P1 0,-5.715; P2 0,-3.175; P3 0,4.445 | hole 2.2: 0,0
2X3 = drill 1.016 pad 1.88 octagon: 1 0,0; 2 0,2.54; 3 2.54,0; 4 2.54,2.54; 5 5.08,0; 6 5.08,2.54
AVR_ICSP = drill 1.016 pad 1.88 octagon: 1 -1.27,5.08; 2 1.27,5.08; 3 -1.27,2.54; 4 1.27,2.54; 5 -1.27,0; 6 1.27,0; 7 -1.27,-2.54; 8 1.27,-2.54; 9 -1.27,-5.08; 10 1.27,-5.08
FIDUCIAL-1X2 = smd 1 x 1: 1 0,0
0603 = smd 0.85 x 0.7: 1 -0.9,0; 2 0.7,0
LED3MM = drill 0.813 octagon: A -1.27,0; K 1.27,0
SOT23-BEC = smd 1 x 1.4: B -0.95,-1.1; C 0,1.1; E 0.95,-1.1
HC49U70 = drill 0.813 round: 1 -2.413,0; 2 2.413,0
R0603 = smd 1 x 1.1: 1 -0.85,0; 2 0.85,0
ALPS_POT_VERTICAL_PS = drill 1 pad 1.88 square: P$1 -2.5,7; P$2 0,7; P$3 2.5,7 | drill 1.5 pad 2.54 octagon: P$4 -4.7,0; P$5 4.7,0
ES_100SP1T6B11M2QEH_SMALL = drill 1.5 pad 2.54 round: O -4.699,0; P 0,0; S 4.699,0
TACTILE-PTH = drill 1.016 pad 1.88 round: 1 -3.251,2.261; 2 3.251,2.261; 3 -3.251,-2.261; 4 3.251,-2.261

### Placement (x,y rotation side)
C1  19.68,98.9 0 top
C2  55.24,97.16 0 top
C3  82.23,85.41 0 top
C4  23.5,85.72 180 top
C5  31.11,85.72 180 top
C6  35.56,84.77 0 top
C7  52.7,82.55 0 top
C8  64.77,82.55 180 top
C9  87.95,80.64 180 top
C10  40.96,80.01 180 top
C11  74.61,79.38 180 top
C12  52.7,79.06 0 top
C13  67.31,78.74 180 top
C14  67.31,73.66 180 top
C15  82.23,64.45 0 top
C16  70.17,63.82 180 top
C17  83.19,61.91 90 top
C18  6.03,62.23 90 top
C19  13.34,62.23 90 top
C20  74.61,59.05 180 top
C21  66.04,56.2 90 top
C22  81.6,45.72 0 top
C23  23.5,45.09 180 top
C24  31.11,45.09 180 top
C25  67.63,44.77 90 top
C26  35.56,44.13 0 top
C27  52.7,41.91 0 top
C28  89.53,40.64 0 top
C29  40.96,39.37 180 top
C30  76.52,39.05 180 top
C31  52.7,38.42 0 top
C32  64.45,37.15 180 top
C33  64.45,35.24 0 top
C34  64.45,33.97 0 top
C35  78.42,24.13 0 top
C36  36.2,20.32 270 top
C37  78.42,22.54 0 top
C38  15.56,20.95 90 top
C39  31.11,20.95 90 top
C40  61.91,19.68 0 top
C41  76.52,14.92 0 top
C42  48.9,14.29 90 top
C43  56.83,11.43 90 top
C44  48.9,11.11 270 top
C45  68.26,2.54 270 top
D1  9.53,21.59 270 top
D2  6.99,20.32 270 top
D3  4.45,19.05 90 top
IC1  55.24,94.3 180 top
IC2  76.2,82.87 270 top
IC3  29.53,82.23 270 top
IC4  46.99,80.64 270 top
IC5  66.99,76.2 270 top
IC6  66.99,71.12 270 top
IC7  76.2,62.55 270 top
IC8  66.99,52.39 0 top
IC9  78.11,42.55 270 top
IC10  29.53,41.59 270 top
IC11  62.55,40.64 90 top
IC12  46.99,40.01 270 top
IC13  63.18,27.94 270 top
IC14  23.5,20.95 180 top
IC15  MCP4822  [SO08']  80.64,18.73 270 top
IC16  65.72,11.43 90 top
J1  9.84,92.71 0 top
J2  22.86,92.71 90 top
J3  34.29,92.71 0 top
J4  75.88,92.71 0 top
J5  9.84,72.39 0 top
J6  22.86,72.39 90 top
J7  34.29,72.39 0 top
J8  75.88,72.39 0 top
J9  9.84,52.07 0 top
J10  22.86,52.07 90 top
J11  34.29,52.07 0 top
J12  75.88,52.07 0 top
J13  9.84,31.75 0 top
J14  22.86,31.75 90 top
J15  34.29,31.75 0 top
J16  75.88,31.75 0 top
J17  88.9,6.99 180 top
J18  81.28,5.08 0 bottom
J19  8.57,8.89 180 bottom
J20  56.52,26.04 270 bottom
JP1  1.91,98.42 0 top
JP2  95.89,98.42 0 top
JP3  95.89,4.45 0 top
JP4  3.17,1.91 0 top
L1  50.8,20 270 top
LED1  15.88,14.61 180 top
LED2  24.13,14.61 180 top
LED3  32.38,14.61 180 top
LED4  40.64,14.61 180 top
Q1  8.57,83.82 0 top
Q2  13.97,83.82 0 top
Q3  8.26,43.81 0 top
Q4  14.29,43.81 0 top
Q5  52.7,12.7 90 top
R1  15.72,95.89 90 top
R2  16.51,98.9 0 top
R3  55.24,98.74 180 top
R4  47.31,92.71 180 top
R5  88.9,92.71 180 top
R6  70.48,84.45 180 top
R7  82.23,83.82 0 top
R8  23.5,84.14 180 top
R9  6.03,83.19 270 top
R10  11.43,83.19 270 top
R11  70.48,82.87 180 top
R12  35.56,83.19 0 top
R13  82.23,82.23 0 top
R14  23.5,82.55 0 top
R15  70.48,81.28 0 top
R16  35.56,81.6 180 top
R17  40.96,81.6 180 top
R18  82.23,80.64 180 top
R19  23.5,80.96 0 top
R20  6.03,80.01 270 top
R21  7.62,80.01 270 top
R22  13.02,80.01 270 top
R23  52.7,80.64 0 top
R24  35.56,80.01 180 top
R25  23.5,79.38 0 top
R26  27.94,77.79 0 top
R27  40.96,78.58 0 top
R28  53.34,77.63 180 top
R29  40.96,76.83 0 top
R30  53.34,75.88 180 top
R31  47.31,72.39 180 top
R32  88.9,72.39 180 top
R33  70.17,65.41 180 top
R34  70.17,62.23 180 top
R35  81.6,61.91 90 top
R36  84.77,61.91 270 top
R37  70.17,60.64 0 top
R38  86.36,60.01 90 top
R39  87.95,60.01 90 top
R40  89.53,60.01 90 top
R41  47.31,52.07 180 top
R42  88.9,52.07 180 top
R43  72.39,44.13 180 top
R44  23.5,43.5 180 top
R45  5.71,43.18 270 top
R46  11.75,43.18 270 top
R47  35.56,42.55 0 top
R48  72.39,42.55 180 top
R49  83.82,42.23 0 top
R50  23.5,41.91 0 top
R51  35.56,40.96 180 top
R52  40.96,40.96 180 top
R53  72.39,40.96 0 top
R54  83.82,40.64 0 top
R55  23.5,40.32 0 top
R56  7.3,40.01 270 top
R57  13.34,40.01 270 top
R58  52.7,40.01 0 top
R59  35.56,39.37 180 top
R60  83.82,39.05 180 top
R61  23.5,38.73 0 top
R62  64.45,38.42 0 top
R63  27.94,37.15 0 top
R64  40.96,37.78 0 top
R65  53.34,36.83 180 top
R66  40.96,36.2 0 top
R67  53.66,34.61 90 top
R68  47.31,31.75 180 top
R69  88.9,31.75 180 top
R70  57.15,15.88 90 top
R71  19.68,15.24 90 top
R72  27.94,15.24 90 top
R73  36.2,15.24 90 top
R74  44.45,15.24 90 top
SW1  61.59,92.71 270 top
SW2  61.59,72.39 90 top
SW3  61.59,52.07 90 top
SW4  15.88,6.99 90 top
SW5  24.13,6.99 90 top
SW6  32.38,6.99 90 top
SW7  40.64,6.99 90 top

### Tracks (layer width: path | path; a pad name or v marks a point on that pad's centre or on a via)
+3V3  (via drill 0.6)
  Top 0.254: C35.1 C37.1 IC15.1 | 16.83,48.58 18.73,46.67 18.73,39.37 v19.05,39.05 20.32,37.78 26.04,37.78 26.35,38.1 28.26,38.1 29.21,39.05 29.21,42.76 29.95,43.5 IC10.8 31.96,43.66 C24.1 | 16.83,48.58 16.19,49.21 16.19,69.53 16.51,69.85 16.51,75.56 17.46,76.52 17.46,80.01 | 50.8,21.27 53.02,19.05 54.61,19.05 56.94,16.73 R70.2 | 5.93,82.23 R9.2 | 5.93,82.23 5.71,82.23 5.08,82.87 5.08,87.31 6.03,88.27 15.88,88.27 17.46,86.68 17.46,80.01 | 17.46,80.01 v18.1,80.01 19.68,78.42 25.08,78.42 25.72,79.06 28.57,79.06 29.21,79.69 29.21,82.55 30.8,84.14 IC3.8 32.13,85.56 C5.1 | R45.2 5.5,42.55 5.08,42.55 4.76,42.86 4.76,46.04 6.35,47.62 12.06,47.62 v13.34,48.9 | v17.14,48.9 16.83,48.58 | C24.1 31.75,45.3 | C24.1 32.13,44.92 | 5.93,82.23 6.03,82.23 R20.1 | v11.43,80.01 R10.2 | v11.75,39.05 R46.2 | C39.+ 31.11,25.08 30.48,25.72 20.64,25.72 15.56,30.8 15.56,38.73 v15.24,39.05
  Top 0.356: v55.88,83.82 53.02,83.82 51.85,82.65 C7.1 | 52.07,42.23 52.07,42.01
  Top 0.406: C36.1 v36.2,23.18 36.02,23.36 C39.+ 29.7,23.36 28.57,22.23 24.13,22.23 23.5,22.86 23.5,24.08 IC14.2 | v41.27,23.18 42.55,21.91 47.31,21.91 48.26,22.86 50.8,22.86 | 50.8,22.86 J20.2 | 59.69,80.01 v59.69,54.61 59.69,46.67 60.33,46.04 v60.33,44.13 60.33,40.01 60.96,39.37 60.96,38.42 | 59.69,80.01 v59.69,83.82 59.69,89.22 60.64,90.17 62.23,90.17 63.5,91.44 63.5,95.25 61.59,97.16 SW1.O | C7.1 IC4.8 | IC12.8 C27.1 51.85,42.01 52.07,42.23 53.02,43.18 v53.98,43.18 | 50.8,22.86 50.8,21.27 L1.1 | v67.31,55.24 66.14,55.24 C21.1 IC8.5 | IC6.5 68.29,73.53 C14.1 68.16,73.76 67.31,74.61 67.31,76.83 67.63,77.15 IC5.5 68.29,78.61 C13.1 68.26,78.84 68.26,79.06 67.31,80.01 59.69,80.01 | C45.1 68.48,3.17 | C37.1 v76.2,22.54 75.56,21.91 75.56,15.03 C41.1 75.56,14.82 75.56,14.29 74.31,13.03 IC16.19 71.51,13.02 | IC16.9 68.12,3.53 C45.1 | 59.37,19.68 C40.1 61.28,19.47 61.28,19.05 61.91,18.41 63.18,18.41 63.32,18.27 IC16.31 | v69.22,7.94 59.37,17.78 59.37,19.68 | 83.5,4.45 v83.5,15.24 | 83.5,4.45 81.6,2.54 v70.17,2.54 69.53,2.54 68.68,3.39 C45.1 | 83.5,4.45 v83.5,2.86 | IC13.16 64.45,32.38 63.6,33.23 C34.1 C33.1 v60.96,35.24 60.96,38.42 | v59.37,20.95 59.37,19.68 | 60.96,38.42 R62.1
  Bottom 0.254: v18.1,80.01 v11.43,80.01 | v13.34,48.9 v17.14,48.9 | v19.05,39.05 v15.24,39.05 v11.75,39.05 | v59.37,20.95 58.1,22.23 55.88,22.23 55.24,22.86 55.24,24.77 J20.2
  Bottom 0.356: v59.69,83.82 v55.88,83.82 | v60.33,44.13 59.37,43.18 v53.98,43.18
  Bottom 0.406: v36.2,23.18 v41.27,23.18 | v67.31,55.24 64.45,55.24 63.82,54.61 v59.69,54.61 | v83.5,15.24 v76.2,22.54 | v70.17,2.54 70.17,6.99 v69.22,7.94 | v83.5,2.86 J18.1 | v60.96,35.24 53.98,28.26 J20.2
ADC_MISO
  Top 0.254: IC16.26 67.32,20.31 65.72,21.91 63.82,21.91 63.18,22.54 63.18,26.35 64.14,27.3 IC13.12
ADC_MOSI
  Top 0.254: IC16.25 68.12,20.46 66.04,22.54 64.14,22.54 63.82,22.86 63.82,25.72 64.14,26.04 IC13.11
ADC_SCK
  Top 0.254: IC16.27 66.52,20.16 65.41,21.27 63.5,21.27 62.55,22.23 62.55,27.3 63.82,28.57 IC13.13
ADC_SS
  Top 0.254: IC13.10 67.63,24.77 69.72,22.67 IC16.23
AREF
  Top 0.254: IC11.1 64.13,39.69 65.09,38.73 65.09,38.63 R62.2 C32.1 66.36,37.15 67.63,35.88 67.63,31.43 67.31,31.11 IC13.15
AREF_-10  (via drill 0.6)
  Top 0.254: v38.73,78.42 39.95,78.42 R27.1 | v55.56,77.47 54.35,77.47 R28.1 | v54.61,73.03 54.61,71.12 53.34,69.85 v44.77,69.85 | v46.99,35.56 46.99,34.29 51.44,29.84 53.02,29.84 54.93,31.75 54.93,36.51 54.61,36.83 R65.1 | v20.32,80.33 20.32,80.01 20.95,79.38 R25.1 | v20.32,77.47 20.64,77.79 R26.1 27.09,77.05 27.3,76.83 v30.48,76.83 | v38.73,37.78 R64.1 | R61.1 22.64,38.31 22.23,38.73 v21.27,38.73 | v31.43,36.83 30.8,36.2 27.3,36.2 26.99,36.51 26.99,37.05 R63.1 21.91,37.15 v21.59,36.83
  Top 0.406: R68.P$3 44.77,24.79 44.77,30.48 45.09,30.8 v45.09,35.56 | v44.77,48.9 44.77,64.45 44.81,64.49 R31.P$3 | R3.2 C2.1 54.3,97.06 IC1.2 49.99,95.4 v44.77,90.17
  Bottom 0.254: 44.77,78.42 v38.73,78.42 32.07,78.42 v30.48,76.83 | v55.56,77.47 54.61,76.52 v54.61,73.03 | 45.09,37.78 v38.73,37.78 32.38,37.78 v31.43,36.83 | v45.09,35.56 v46.99,35.56 | v20.32,77.47 20.64,77.79 20.64,80.01 v20.32,80.33 | v21.27,38.73 21.59,38.42 v21.59,36.83
  Bottom 0.406: v44.77,48.9 44.77,45.11 R41.P$3 45.09,44.79 45.09,37.78 v45.09,35.56 | R31.P$3 44.81,66 44.77,66.04 v44.77,69.85 44.77,78.42 44.77,84.77 44.81,84.81 R4.P$3 44.77,85.75 v44.77,90.17
CH1
  Top 0.254: R8.2 C4.2 22.64,86.14 23.18,86.68 26.67,86.68 | IC3.1 26.67,84.39 26.67,86.68 | IC13.1 59.69,32.38 59.37,32.7 59.37,39.05 59.05,39.37 59.05,42.86 58.1,43.81 58.1,84.14 56.83,85.41 52.7,85.41 51.44,84.14 41.27,84.14 37.15,88.27 28.26,88.27 26.67,86.68
CH2
  Top 0.254: IC13.2 59.05,31.11 58.74,31.43 58.74,38.73 58.42,39.05 58.42,42.55 57.47,43.5 57.47,83.82 56.52,84.77 53.02,84.77 51.75,83.5 37.47,83.5 37.15,83.19 R12.2 C6.2 36.41,85.51 36.2,85.72 33.97,85.72 33.66,85.41 33.66,83.19 33.34,82.87 IC3.7
CH3
  Top 0.254: 26.99,46.04 28.57,47.62 37.15,47.62 41.27,43.5 51.12,43.5 52.7,45.09 54.93,45.09 55.56,44.45 55.56,42.55 56.52,41.59 56.52,38.1 56.83,37.78 56.83,30.16 58.42,28.57 58.42,27.94 59.05,27.3 IC13.5 | R44.2 C23.2 22.64,45.82 22.86,46.04 26.99,46.04 | IC10.1 26.99,43.56 26.99,46.04
CH4
  Top 0.254: IC10.7 33.34,42.23 33.66,42.55 33.66,44.77 33.97,45.09 36.2,45.09 36.41,44.87 C26.2 R47.2 37.15,42.55 37.47,42.86 51.44,42.86 53.02,44.45 54.29,44.45 54.93,43.81 54.93,42.23 55.88,41.27 55.88,37.78 56.2,37.47 56.2,29.84 57.78,28.26 57.78,27.62 58.74,26.67 58.74,26.35 59.05,26.04 IC13.6
CH5
  Top 0.254: IC4.7 50.8,81.28 51.12,81.6 53.34,81.6 53.55,81.38 R23.2 C12.2 55.88,79.06 56.83,78.11 56.83,43.18 57.78,42.23 57.78,38.73 58.1,38.42 58.1,30.8 59.05,29.84 IC13.3
CH6
  Top 0.254: C10.2 R17.2 40.11,82.33 40.32,82.55 IC4.1 45.72,82.55 46.04,82.23 46.04,79.06 50.8,74.3 55.24,74.3 56.2,73.34 56.2,42.86 57.15,41.91 57.15,38.42 57.47,38.1 57.47,30.48 59.37,28.57 IC13.4
CH7
  Top 0.254: IC12.7 50.8,40.64 51.12,40.96 53.02,40.96 53.55,40.42 R58.2 C31.2 54.29,38.42 55.56,37.15 55.56,29.53 57.15,27.94 57.15,27.3 58.1,26.35 58.1,25.72 59.05,24.77 IC13.7
CH8  (via drill 0.6)
  Top 0.254: C29.2 R52.2 40.11,41.7 40.32,41.91 IC12.1 45.72,41.91 46.04,41.59 46.04,34.29 52.7,27.62 v55.56,27.62 | v57.78,24.77 58.42,24.13 58.42,23.81 58.74,23.5 IC13.8
  Bottom 0.254: v57.78,24.77 57.78,26.67 56.83,27.62 v55.56,27.62
CHANNEL1
  Top 0.254: IC5.4 68.9,75.25 69.22,75.56 69.22,79.69 67.94,80.96 64.14,80.96 63.17,81.93 C8.+
CHANNEL1_BUFFERED
  Top 0.254: R11.2 R6.2 69.53,84.56 69.53,93.98 72.71,97.16 J4.P3
CHANNEL1_RETURN
  Top 0.254: R5.P$2 88.9,84.45 90.17,83.19 91.12,83.19 92.71,81.6 92.71,79.06 91.12,77.47 91.12,71.44 93.34,69.22 93.34,60.96 91.54,59.16 R40.1
CHANNEL2
  Top 0.254: IC6.4 68.58,70.17 69.22,70.8 69.22,73.98 70.8,75.56 78.42,75.56 79.38,76.52 83.19,76.52 86.35,79.68 C9.+
CHANNEL2_BUFFERED  (via drill 0.6)
  Top 0.254: R7.2 R13.2 83.4,82.55 90.81,82.55 92.08,81.28 92.08,79.38 91.44,78.74 86.36,78.74 83.5,75.88 79.69,75.88 v78.42,74.61
  Bottom 0.254: v78.42,74.61 76.2,76.83 J8.P3
CHANNEL2_RETURN
  Top 0.254: R36.1 84.88,62.87 87.63,62.87 88.9,64.14 R32.P$2
CHANNEL3
  Top 0.254: IC8.4 68.55,53.69 69.22,53.02 69.22,49.53 67.63,47.94 C25.+
CHANNEL3_BUFFERED  (via drill 0.6)
  Top 0.254: R48.2 R43.2 71.75,44.35 v71.75,56.52
  Bottom 0.254: v71.75,56.52 J12.P3
CHANNEL3_RETURN
  Top 0.254: R42.P$2 88.9,51.75 87.31,53.34 87.31,57.47 86.36,58.42 R38.1
CHANNEL4
  Top 0.254: IC15.8 83.5,20.85 83.5,21.91 81.92,23.5 81.92,25.4 77.79,29.53 77.79,33.66 78.74,34.61 86.68,34.61 91.14,39.06 C28.+
CHANNEL4_BUFFERED
  Top 0.254: R54.2 R49.2 88.9,42.23 89.53,41.59 89.53,38.42 86.36,35.24 76.83,35.24 J16.P3
CHANNEL4_RETURN
  Top 0.254: R69.P$2 88.9,32.7 94.61,38.42 94.61,46.99 87.95,53.66 R39.1
COARSE1
  Top 0.254: R4.P$2 47.31,86.68 46.67,87.31 39.05,87.31 35.56,90.81 22.23,90.81 19.05,93.98 17.46,93.98 17.14,93.66 17.14,90.49 19.37,88.27 19.37,82.87 21.27,80.96 R19.1
COARSE2
  Top 0.254: R31.P$2 47.31,66.99 46.04,68.26 42.23,68.26 39.37,71.12 39.37,73.98 37.47,75.88 37.47,81.28 37.15,81.6 R16.1
COARSE3
  Top 0.254: R41.P$2 47.31,46.2 46.99,46.51 39.21,46.51 35.56,50.16 22.23,50.16 19.05,53.34 17.78,53.34 17.14,52.7 17.14,50.48 19.37,48.26 19.37,43.18 22.23,40.32 R55.1
COARSE4
  Top 0.254: R51.1 36.83,40.96 37.47,40.32 37.47,29.53 43.81,23.18 46.67,23.18 47.31,23.81 R68.P$2
CV1  (via drill 0.6)
  Top 0.254: R14.1 v21.27,82.55 20,83.82 20,88.58 18.41,90.17 J2.P3
  Bottom 0.254: J6.P2 26.04,78.42 21.91,82.55 v21.27,82.55
CV2
  Top 0.254: R24.1 36.51,79.91 36.51,76.2 35.24,74.93 33.34,74.93 28.57,70.17 26.04,70.17 | 26.04,70.17 20.64,70.17 J6.P3 | J10.P2 26.04,70.17
CV3  (via drill 0.6)
  Top 0.254: R50.1 21.91,41.91 v21.27,42.55 20,43.81 20,48.58 18.41,50.16 J10.P3
  Bottom 0.254: J14.P2 26.04,37.78 v21.27,42.55
CV4  (via drill 0.6)
  Top 0.254: R59.1 36.51,39.37 36.51,38.73 35.56,37.78 33.97,37.78 31.43,35.24 20,35.24 19.05,36.2 v19.05,36.51
  Bottom 0.254: v19.05,36.51 18.41,35.88 J14.P3
DAC_MOSI
  Top 0.254: IC16.17 76.83,11.43 78.74,13.34 78.74,16.51 78.42,16.83 IC15.4
DAC_SCK
  Top 0.254: 71.53,9.84 IC16.15 73.01,9.83 73.34,10.16 77.47,10.16 80.01,12.7 80.01,17.46 79.38,18.1 IC15.3 77.15,18.1
DAC_SS
  Top 0.203: 79.06,17.46 76.2,17.46
  Top 0.229: 79.38,17.14 79.06,17.46 | 76.2,17.46 76.2,19.37
  Top 0.254: 79.38,17.14 79.38,13.02 77.15,10.79 73.03,10.79 72.86,10.63 IC16.16 | 76.2,19.37 IC15.2
FM1  (via drill 0.6)
  Top 0.254: v48.26,88.27 47.94,87.95 39.37,87.95 36.51,90.81 36.51,96.2 35.56,97.16 J3.P3 | v47.31,81.28 47.31,78.74 51.12,74.93 53.66,74.93 54.19,75.46 R30.1
  Bottom 0.254: v47.31,81.28 49.85,83.82 50.8,83.82 51.44,84.45 51.44,86.68 49.85,88.27 v48.26,88.27
FM2  (via drill 0.6)
  Top 0.254: v38.73,76.83 R29.1
  Bottom 0.254: J7.P3 v38.73,76.83
FM3  (via drill 0.6)
  Top 0.254: R67.1 53.55,33.66 50.8,33.66 47.31,37.15 v47.31,40.64 | v48.26,47.62 47.94,47.31 43.5,47.31 J11.P3
  Bottom 0.254: v47.31,40.64 49.85,43.18 50.48,43.18 51.44,44.13 51.44,46.04 49.85,47.62 v48.26,47.62
FM4  (via drill 0.6)
  Top 0.254: v38.73,36.2 R66.1
  Bottom 0.254: J15.P3 v38.73,36.2
GATE1
  Top 0.254: IC16.40 58.57,10.63 55.88,7.94 48.26,7.94 47.31,8.89 47.31,17.78 44.77,20.32 41.91,20.32 39.05,23.18 39.05,25.72 34.92,29.84 21.59,29.84 20.32,31.11 20.32,32.7 18.1,34.92 18.1,46.35 15.56,48.9 15.56,69.85 15.88,70.17 15.88,75.88 16.83,76.83 16.83,84.77 15.56,86.04 11.75,86.04 10.79,85.09 8.74,85.09 Q1.C 8.4,85.09 6.35,85.09 6.03,84.77 R9.1
GATE1_IN
  Top 0.254: R21.2 7.62,78.42 7.3,78.11 3.81,78.11 | 3.81,78.11 3.81,94.3 6.67,97.16 J1.P3 | 3.81,78.11 3.81,73.34 7.94,69.22 J5.P2
GATE1_LED
  Top 0.254: LED4.A 43.4,16.09 R74.2
GATE2
  Top 0.254: IC16.41 58.73,9.83 56.2,7.3 47.94,7.3 46.67,8.57 46.67,17.46 44.45,19.68 41.59,19.68 38.42,22.86 38.42,24.77 35.88,27.3 33.66,27.3 33.34,27.62 21.59,27.62 19.68,29.53 19.68,32.38 17.46,34.61 17.46,46.04 14.92,48.58 14.92,70.17 15.24,70.48 15.24,76.2 16.19,77.15 16.19,84.45 15.73,84.92 Q2.C 13.8,85.09 11.75,85.09 11.43,84.77 R10.1
GATE2_IN
  Top 0.254: 13.02,76.83 13.02,67.63 9.84,64.45 9.84,59.05 12.06,56.83 12.06,51.44 9.84,49.21 J9.P2 | 13.02,76.83 R22.2 | 13.02,76.83 J5.P3
GATE2_LED
  Top 0.254: LED3.A 35.14,16.09 R73.2
GATE3
  Top 0.254: 59.78,8.89 IC16.42 58.88,9.03 56.52,6.67 47.62,6.67 46.04,8.26 46.04,17.14 44.13,19.05 41.27,19.05 37.78,22.54 37.78,23.81 36.83,24.77 33.34,24.77 31.11,26.99 21.27,26.99 16.83,31.43 16.83,45.4 16.19,46.04 11.75,46.04 10.62,44.91 Q3.C 8.09,45.09 6.03,45.09 5.71,44.77 R45.1
GATE3_IN
  Top 0.254: J13.P2 8.57,28.57 7.3,29.84 R56.2 7.2,39.05 6.67,39.05 4.13,41.59 4.13,51.75 8.89,56.52 J9.P3
GATE3_LED
  Top 0.254: LED2.A 26.89,16.09 R72.2
GATE4
  Top 0.254: IC16.43 59.03,8.23 56.83,6.03 47.31,6.03 45.4,7.94 45.4,16.83 43.81,18.41 40.96,18.41 37.15,22.23 37.15,23.5 36.51,24.13 33.02,24.13 30.8,26.35 20.95,26.35 16.19,31.11 16.19,44.45 15.73,44.91 Q4.C 14.12,45.09 12.06,45.09 11.75,44.77 R46.1
GATE4_IN
  Top 0.254: J13.P3 11.43,36.2 13.34,38.1 R57.2
GATE4_LED
  Top 0.254: LED1.A 18.63,16.09 R71.2
GND  (via drill 0.6)
  Top 0.406: 54.61,40.85 54.61,40.64
  other vias: 58.1,12.38 64.45,19.37 76.83,13.34 66.67,1.59 15.24,40.96 28.57,86.68 28.73,46.2 43.18,76.2 30.16,40.64 43.81,36.83 50.48,77.15 50.16,36.83 56.2,81.92 60.33,22.23 50.8,12.7 7.62,62.23 12.06,62.23 62.23,36.51 75.88,24.45 62.23,43.18 67.15,49.21 67.63,57.15 65.72,68.58 64.77,73.66 65.09,78.74 76.2,82.87 76.2,60.64 78.11,42.55 78.74,37.78 83.19,67.31 83.19,87 85.72,19.68 63.82,9.53 66.36,8.26 67.63,13.34 29.84,15.88 38.73,16.51 13.97,16.51 17.46,19.05 33.66,19.05 27.94,24.13 83.82,45.72 91.44,62.23 1.27,101.6 1.27,1.27 1.27,91.44 1.27,71.12 1.27,50.8 1.27,40.64 1.27,30.48 1.27,10.16 21.59,1.27 71.44,1.27 96.52,1.27 96.52,10.16 96.52,20.32 96.52,30.48 96.52,40.64 96.52,50.8 96.52,60.96 96.52,71.12 96.52,81.28 96.52,91.44 96.52,101.6 85.09,101.6 74.93,101.6 18.1,96.2 57.78,94.61 88.9,97.79 38.1,59.69 38.1,69.85 88.9,19.05 88.9,90.17 66.04,90.17 40.64,90.17 48.9,20.95 53.34,64.77 53.34,54.61 64.14,29.84 71.75,6.03 76.2,64.14 14.92,80.96 8.89,40.96 1.27,60.96 31.11,52.7 78.11,59.05 78.11,79.38 72.07,67.94 74.61,67.94 72.07,77.15 65.09,14.61 7.62,73.66 4.76,33.02 67.94,22.23 54.93,40.64 49.53,90.17 30.16,80.96 46.04,76.2 14.61,78.11 21.11,87.47 20.95,47.15 41.91,85.72 41.91,45.09
  pour Bottom: 0,102.87 0,0 97.79,0 97.79,102.87
  pour Top (isolate 0.203): 0,102.87 0,0 97.79,0 97.79,102.87
MIDI_IN
  Top 0.254: IC16.12 74.17,7.43 75.25,6.35 77.47,6.35 J18.3
MIX  (via drill 0.6)
  Top 0.254: v95.25,66.67 95.25,30.48 93.34,28.57 93.34,6.99 J17.P3 | v88.9,69.22 80.96,69.22 76.83,65.09 73.34,65.09 72.07,66.36 69.85,66.36 69.53,66.04 69.53,65.62 R33.2 68.58,65.41 68.26,65.09 68.26,62.55 68.58,62.23 R34.2
  Bottom 0.254: v95.25,66.67 92.71,69.22 v88.9,69.22
N$1
  Top 0.254: 7.62,80.75 R21.1 Q1.B
N$2
  Top 0.254: Q2.B R22.1 13.02,80.75
N$3
  Top 0.254: 7.3,40.74 R56.1 Q3.B
N$4
  Top 0.254: R32.P$1 91.4,69.57 85.72,75.25 80.64,75.25 79.06,73.66 79.06,72.71 79.06,72.52 79.06,72.39 J8.P2
N$5
  Top 0.254: IC16.44 59.18,7.43 57.15,5.4 46.99,5.4 44.77,7.62 44.77,13.02 44.45,13.34 R74.1
N$6
  Top 0.254: R73.1 36.2,13.65 36.51,13.34 39.69,13.34 41.27,11.75 41.27,7.62 41.91,6.99 44.45,6.99 46.67,4.76 60.64,4.76 61.51,5.63 IC16.1
N$7
  Top 0.254: R72.1 27.94,13.65 28.89,12.7 39.37,12.7 40.64,11.43 40.64,6.99 41.27,6.35 44.13,6.35 46.35,4.13 60.96,4.13 | 60.96,4.13 60.98,4.1 | 60.96,4.13 61.91,4.13 62.52,4.74 IC16.2
N$8
  Top 0.254: R71.1 19.68,13.65 21.27,12.06 39.05,12.06 40.01,11.11 40.01,6.67 40.96,5.71 43.81,5.71 46.04,3.49 62.23,3.49 63.32,4.58 IC16.3
N$9
  Top 0.254: R50.2 R55.2 R61.2 | R50.2 R44.1 C23.1 | IC10.2 25.72,42.23 25.4,41.91 R50.2
N$11
  Top 0.254: IC4.2 42.86,81.28 42.55,81.6 R17.1 C10.1 R27.2 R29.2
N$12
  Top 0.254: R20.2 5.93,79.06 5.4,79.06 4.45,80.01 4.45,87.95 6.03,89.53 J1.P2
N$13
  Top 0.254: R51.2 R47.1 C26.1 | R51.2 R59.2 34.71,38.84 34.29,38.42 31.11,38.42 29.84,37.15 R63.2 | R51.2 IC10.6
N$15
  Top 0.254: IC12.6 50.8,39.37 51.44,40.01 R58.1 C31.1 51.85,38 52.39,37.47 52.39,36.93 R65.2 52.39,36.73 52.39,36.2 53.12,35.46 R67.2
N$18
  Top 0.254: IC12.2 42.86,40.64 42.55,40.96 R52.1 C29.1 R64.2 R66.2
N$19
  Top 0.254: 71.66,8.89 IC16.14 73.17,9.03 73.66,9.53 77.79,9.53 80.64,12.38 80.64,24.77 78.11,27.3 71.75,27.3 68.9,30.16 68.9,37.47 65.41,40.96 65.41,43.5 64.45,44.45 64.45,71.44 65.08,72.07 IC6.1
N$20
  Top 0.254: R15.1 69.22,81.28 67.94,82.55 C8.-
N$21  (via drill 0.6)
  Top 0.254: v66.99,52.39 IC8.2
  Bottom 0.254: v66.99,52.39 61.91,52.39 SW3.P
N$22
  Top 0.254: R15.2 R11.1 72.07,82.87 72.71,83.5 IC2.2
N$23
  Top 0.254: R6.1 71.65,84.77 IC2.1
N$24  (via drill 0.6)
  Top 0.254: v66.99,71.12 IC6.2
  Bottom 0.254: v66.99,71.12 62.87,71.12 SW2.P
N$25
  Top 0.254: R18.1 83.19,80.64 84.45,81.92 89.22,81.92 89.55,81.58 C9.-
N$26
  Top 0.254: R18.2 R13.1 IC2.6
N$27
  Top 0.254: IC2.7 80.01,83.5 80.33,83.82 R7.1
N$28
  Top 0.254: R53.1 68.58,40.96 67.63,41.91 C25.-
N$29
  Top 0.254: IC4.6 50.8,80.01 51.44,80.64 R23.1 C12.1 51.85,78.64 52.39,78.11 52.39,77.73 R28.2 R30.2
N$30
  Top 0.254: R53.2 R48.1 73.56,42.86 73.98,42.86 74.3,43.18 IC9.2
N$31
  Top 0.254: R43.1 73.56,44.45 IC9.1
N$32
  Top 0.254: R60.1 87.31,39.05 87.94,39.67 C28.-
N$33
  Top 0.254: R60.2 R54.1 81.7,41.91 IC9.6
N$34
  Top 0.254: R49.1 82.02,43.18 IC9.7
N$35
  Top 0.254: IC7.6 80.01,61.91 80.86,61.06 R35.1 C17.1 R36.2 84.98,60.86 R38.2 R39.2 R40.2
N$36
  Top 0.254: IC7.2 72.39,63.18 71.75,63.82 C16.1 R34.1 R37.2
N$37
  Top 0.254: IC7.1 72.39,64.45 71.44,65.41 R33.1 70.91,65.41 C16.2
N$38
  Top 0.406: D1.C 9.66,23.36 C38.+ 15.7,23.5 17.46,23.5 18.07,24.11 IC14.3
N$39  (via drill 0.6)
  Top 0.406: v55.56,10.16 55.98,10.58 C43.1 56.94,10.48 57.47,10.48 58.42,11.43 IC16.39 | v55.56,15.24 55.56,16.51 54.29,17.78 51.44,17.78 50.8,18.41 L1.2
  Bottom 0.406: v55.56,10.16 v55.56,15.24
N$40
  Top 0.254: R5.P$1 91.4,87.35 90.17,88.58 84.77,88.58 83.82,89.53 J4.P2
N$41
  Top 0.254: IC16.10 68.9,5.61 68.9,4.76 69.85,3.81 70.8,3.81 71.44,3.17 81.28,3.17 82.87,4.76 82.87,8.57 81.28,10.16 81.28,25.08 76.52,29.84 70.17,29.84 69.53,30.48 69.53,37.78 66.04,41.27 66.04,41.28 IC8.1
N$42
  Top 0.254: C17.2 R35.2 80.43,62.76 80.01,63.18 IC7.7 77.15,63.18 75.25,61.28 72.23,61.28 72.07,61.12 72.07,60.01 71.75,59.69 69.85,59.69 69.32,60.22 R37.1
N$43
  Top 0.254: R42.P$1 91.4,44.09 90.81,43.5 84.77,43.5 84.45,43.81 79.38,43.81 78.42,44.77 78.42,46.99 76.52,48.9 J12.P2
N$44  (via drill 0.6)
  Top 0.254: R69.P$1 91.4,23.45 90.81,22.86 83.5,22.86 82.55,23.81 82.55,25.72 79.69,28.57 v79.69,29.53
  Bottom 0.254: v79.69,29.53 78.74,28.57 J16.P2
N$45
  Top 0.254: R16.2 R12.1 C6.1 | R24.2 R16.2 | R24.2 34.71,80.11 | R16.2 IC3.6 | R26.2 29.53,77.79 30.48,78.74 34.29,78.74 34.71,79.16 R24.2
N$46
  Top 0.254: 15.72,98.9 R2.1 15.66,97.79 | R1.2 15.66,96.79 15.66,97.79 | 15.66,97.79 18.73,97.79 | 18.73,97.79 22.23,97.79 26.04,93.98 J2.P2 | C1.1 18.73,98.8 18.73,97.79
N$47
  Top 0.406: J19.1 J19.2 10.79,3.81 11.43,4.45 11.43,15.24 10.16,16.51 7.94,16.51 6.99,17.46 D2.A
N$48
  Top 0.254: 71.66,13.97 IC16.20 72.89,13.83 73.34,14.29 73.34,22.86 68.26,27.94 68.26,37.15 64.77,40.64 64.77,42.86 63.82,43.81 63.82,56.83 | 63.82,74.87 63.82,74.93 65.09,76.2 IC5.2 | 63.82,74.87 SW2.S | 63.82,56.83 63.82,74.87 | SW3.S 61.66,56.83 63.82,56.83
N$49
  Top 0.406: D3.C 4.45,15.88 6.35,13.97 J19.9 J19.10
N$50
  Top 0.254: C4.1 R8.1 R14.2 | R14.2 25.08,82.55 25.4,82.87 IC3.2 | R14.2 R19.2 R25.2
N$82
  Top 0.254: IC16.37 59.91,13.02 58.74,13.02 58.42,13.34 54.61,13.34 52.7,11.43 Q5.1 48.92,10.29 C44.2
N$83
  Top 0.254: IC16.36 58.88,13.83 58.74,13.97 53.98,13.97 52.83,15.11 Q5.2 52.68,15.14 C42.2
N$40000
  Top 0.254: 13.34,40.74 R57.1 Q4.B
NES_TRIANGLE_CLK  (via drill 0.6)
  Top 0.254: v68.9,11.43 68.92,11.46 IC16.24
  Bottom 0.254: J18.4 77.47,8.89 71.44,8.89 v68.9,11.43
PDICLK
  Top 0.254: 59.9,14.61 IC16.35 58.4,14.63 58.1,14.92 | J20.5 56.52,20.32 58.1,18.73 58.1,14.92 | R70.1 57.25,14.92 58.1,14.92
PDIDATA
  Top 0.254: 60.01,15.52 IC16.34 59.18,15.43 58.74,15.88 58.74,19.05 57.78,20 57.78,21.59 57.15,22.23 55.88,22.23 55.24,22.86 55.24,24.77 J20.1
SW1
  Top 0.254: IC16.4 64.12,4.43 62.55,2.86 45.72,2.86 43.5,5.08 39.69,5.08 38.38,3.77 SW7.1 SW7.2
SW2
  Top 0.254: IC16.5 64.92,4.28 62.87,2.22 31.43,2.22 30.12,3.53 SW6.1 SW6.2
SW3
  Top 0.254: IC16.6 65.72,4.13 63.18,1.59 23.81,1.59 21.87,3.53 SW5.1 SW5.2
SW4
  Top 0.254: IC16.7 66.52,3.98 63.5,0.95 23.5,0.95 22.23,2.22 14.92,2.22 13.65,3.49 13.61,3.49 SW4.1 SW4.2
SW_MIDI_LEARN
  Top 0.254: IC16.11 70.25,5.63 72.07,3.81 79.38,3.81 80.01,4.45 80.01,5.71 81.28,6.99 J18.2
SW_MIDI_MODE
  Top 0.254: IC16.13 75.59,8.23 J18.6
SYNC_SWITCH
  Top 0.254: IC16.28 65.72,20 65.09,20.64 63.18,20.64 61.91,21.91 61.91,33.02 61.59,33.34 60.33,33.34 60.01,33.66 60.01,39.37 59.69,39.69 59.69,43.18 58.74,44.13 58.74,89.85 SW1.P
VCC  (via drill 0.6)
  Top 0.254: 17.14,100.01 17.14,99.06 | 17.14,99.06 17.14,98.96 | R2.2 17.2,99.06 17.14,99.06
  Top 0.406: 3.17,64.77 3.17,60.96 3.49,60.64 3.49,23.18 4.45,22.22 D2.C 7.94,22.22 9.53,20.64 D1.A | 3.17,64.77 3.17,94.61 8.57,100.01 17.14,100.01 v80.64,100.01 | v80.64,87 81.38,86.26 C3.1 80.64,85.41 80.01,84.77 IC2.8 | v80.64,58.74 80.64,46.35 80.75,46.25 C22.1 80.75,44.49 IC9.8 | 6.53,64.63 C18.+ 5.89,64.77 3.17,64.77 | IC7.8 C15.1 81.38,66.25 v80.64,66.99
  Bottom 0.406: v80.64,58.74 v80.64,66.99 v80.64,87 v80.64,100.01
VEE  (via drill 0.6)
  Top 0.406: C19.- 13.2,59.69 v11.43,59.69 | 75.5,39.22 C30.2 | IC2.4 73.6,79.54 C11.2 v72.39,79.38 | 75.5,39.22 75.34,39.05 v74.3,39.05 | v72.07,58.74 73.34,58.74 | 73.34,58.74 73.34,46.2 v72.71,46.2 | 75.5,39.22 IC9.4 | IC7.4 73.6,59.22 C20.2 73.66,59.05 73.34,58.74 | v57.47,101.12 8.1,101.12 2.38,95.41 v2.38,59.69 2.38,21.75 3.18,20.95 D3.A | v57.47,98.74 R3.1 | v57.47,101.12 | v57.47,101.12 v73.34,101.12
  Bottom 0.406: v2.38,59.69 v11.43,59.69 | 73.34,79.38 v72.39,79.38 | v73.34,101.12 73.34,79.38 | v74.3,39.05 73.34,40.01 73.34,46.2 v72.71,46.2 | 73.34,79.38 73.34,60.01 v72.07,58.74 | v57.47,101.12 v57.47,98.74

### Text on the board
bPlace: PDI | Red stripe
tNames: Edges | cc-by-sa Olivier Gillet, 2014. v2
bNames: Edges | cc-by-sa Olivier Gillet, 2014. v2 | -12V | GND | GND | GND | +12V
